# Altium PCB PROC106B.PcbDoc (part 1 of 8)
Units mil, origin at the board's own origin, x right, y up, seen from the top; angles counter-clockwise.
Board outline 4498.18 x 1060.53 mil, 8 copper layers (Top Layer, GND1, Sig1, PWR1, PWR2, Sig2, GND2, Bottom Layer), stack 69.602 mil thick; 439 components, 327 nets, 1548 pads, 843 vias.
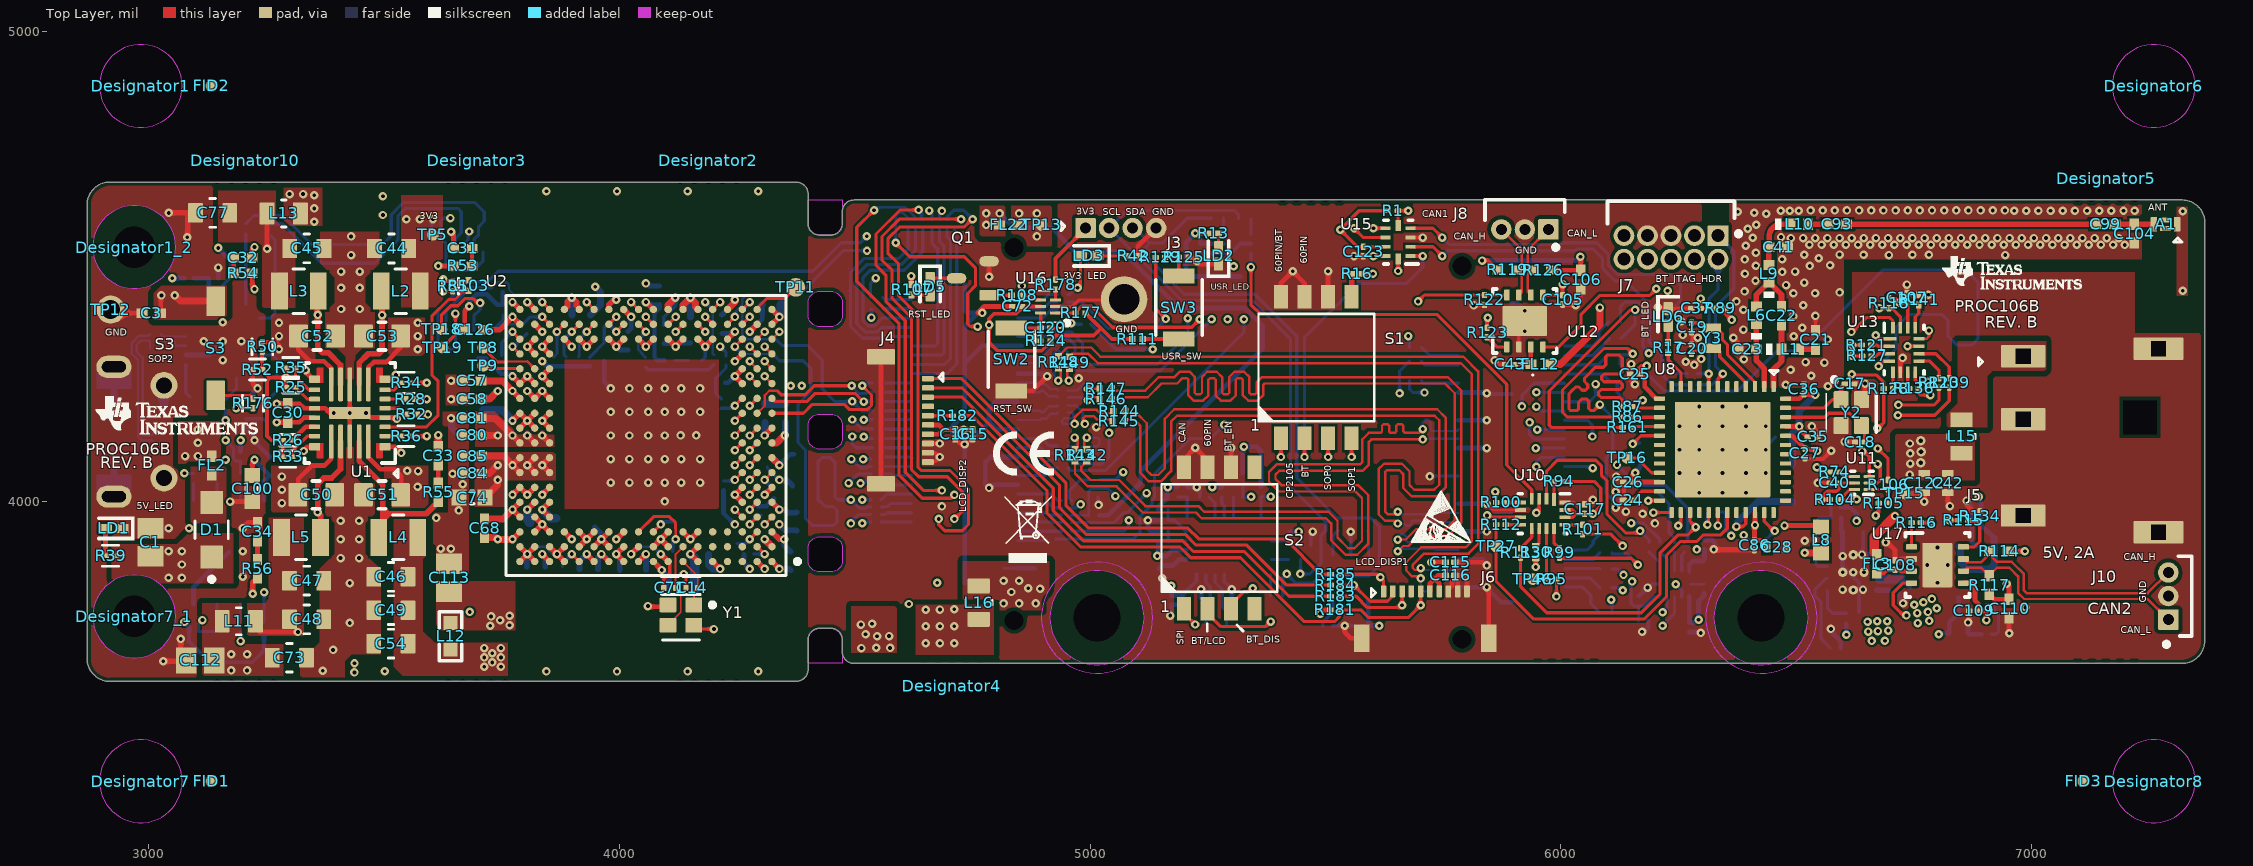
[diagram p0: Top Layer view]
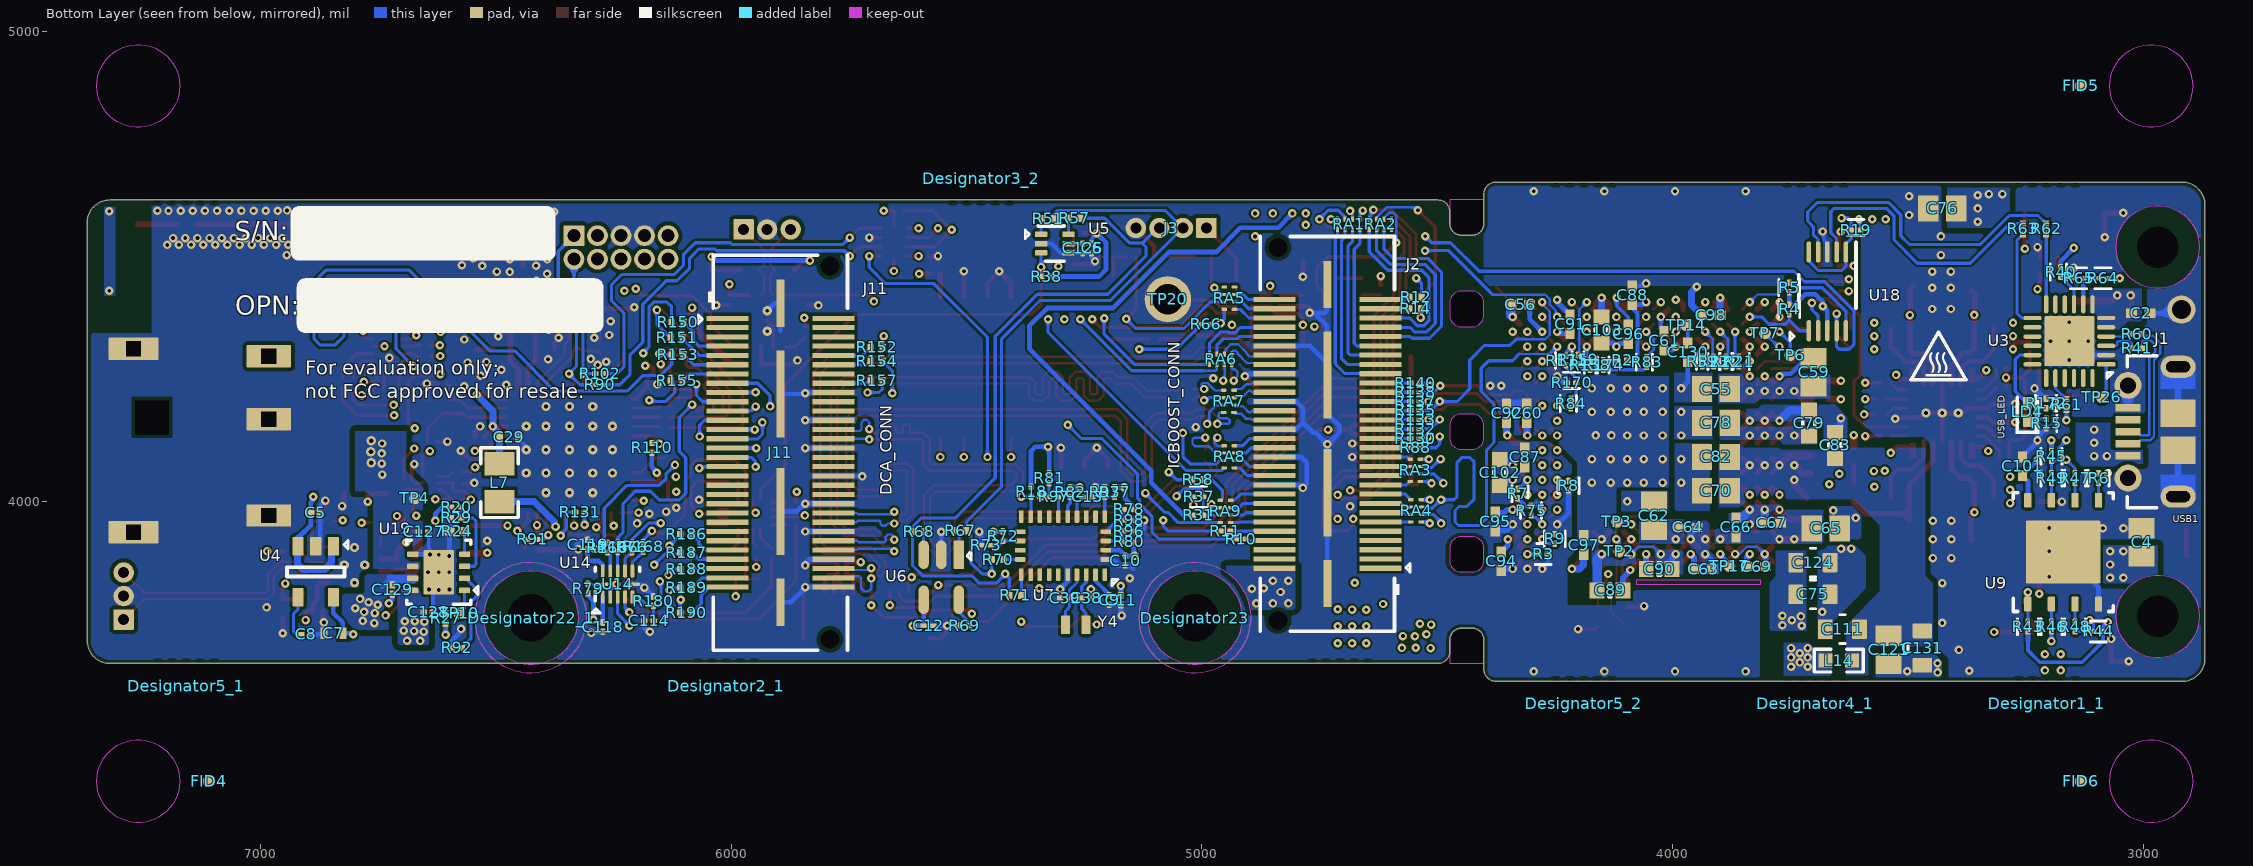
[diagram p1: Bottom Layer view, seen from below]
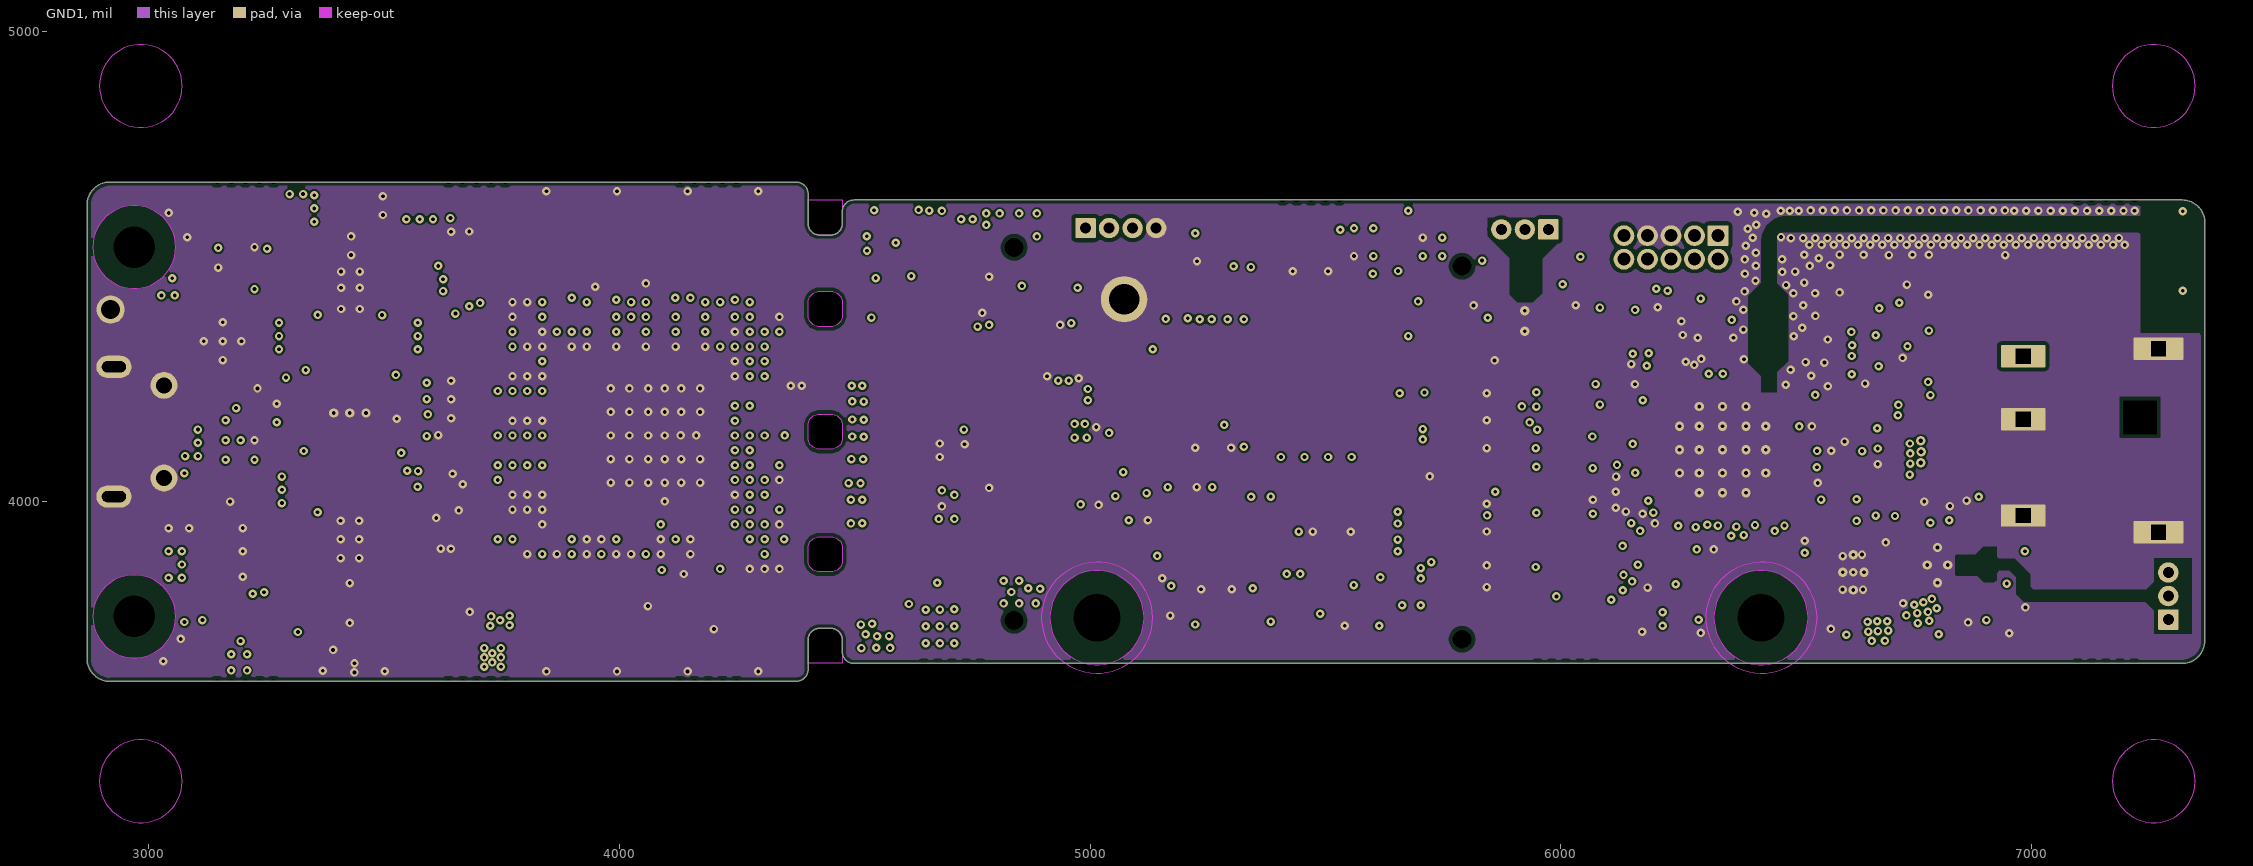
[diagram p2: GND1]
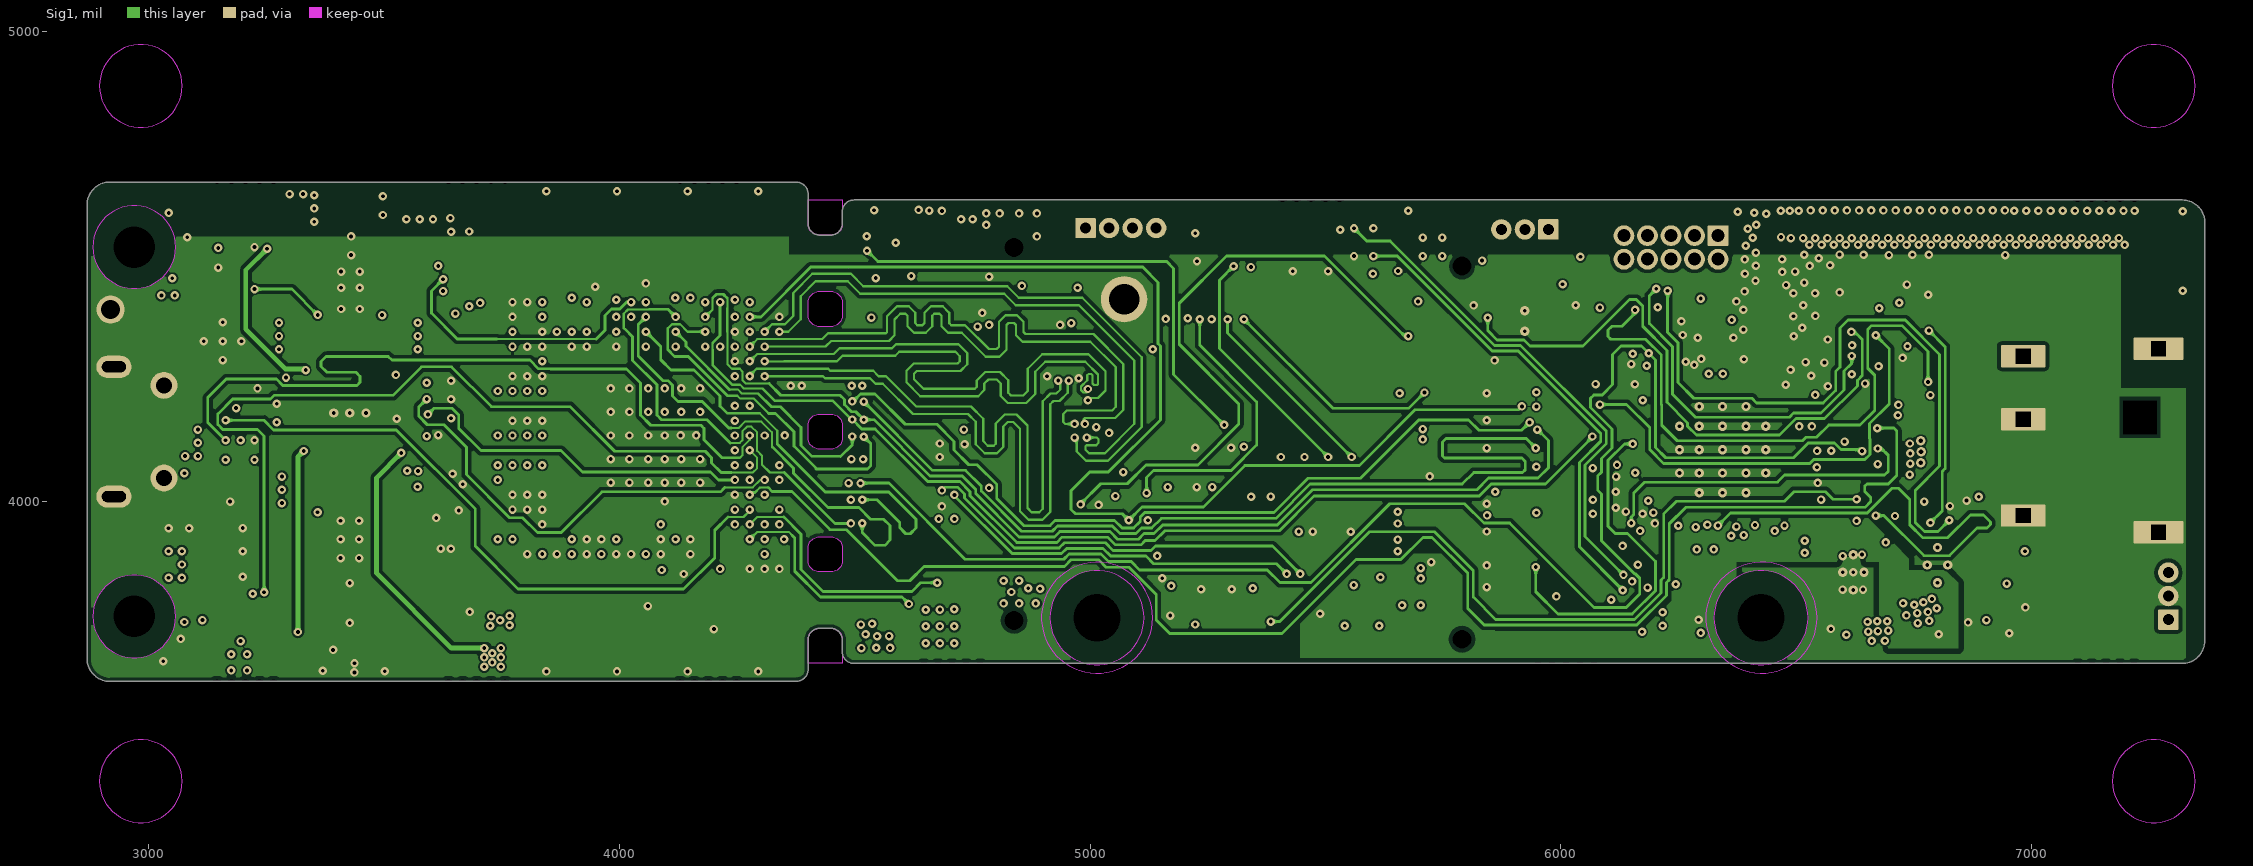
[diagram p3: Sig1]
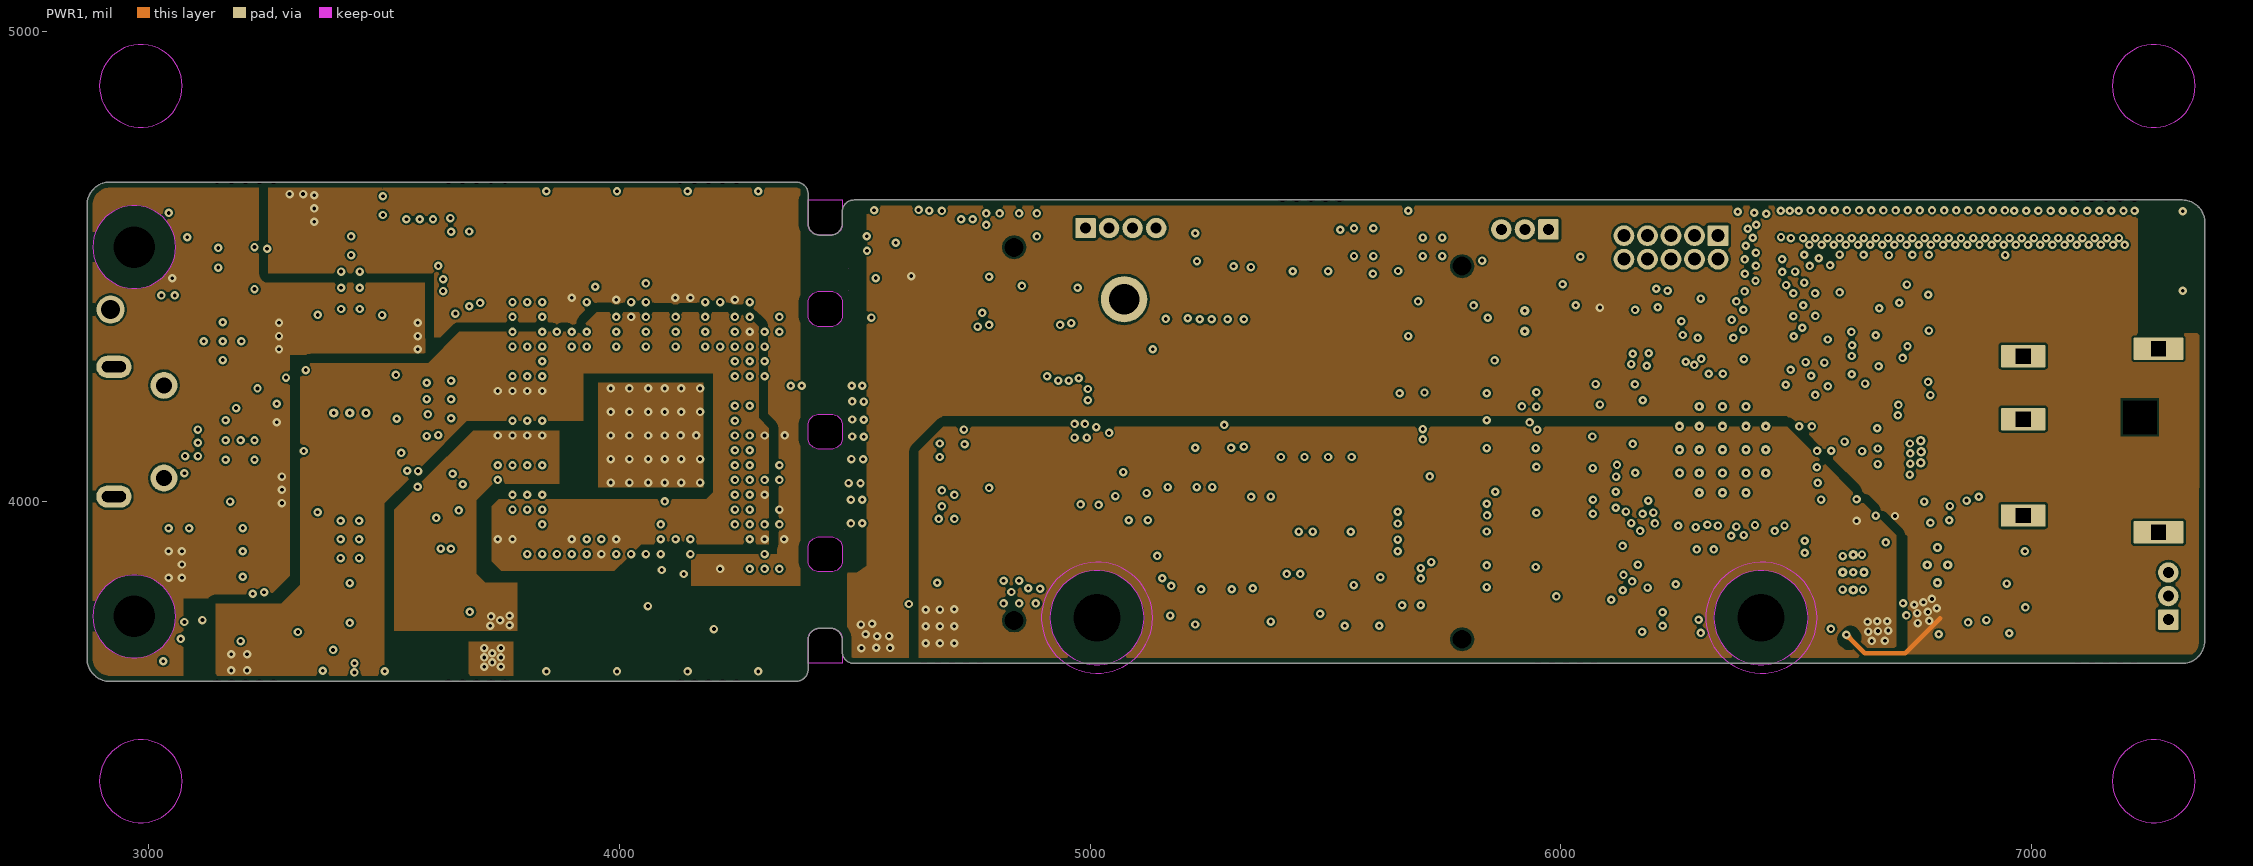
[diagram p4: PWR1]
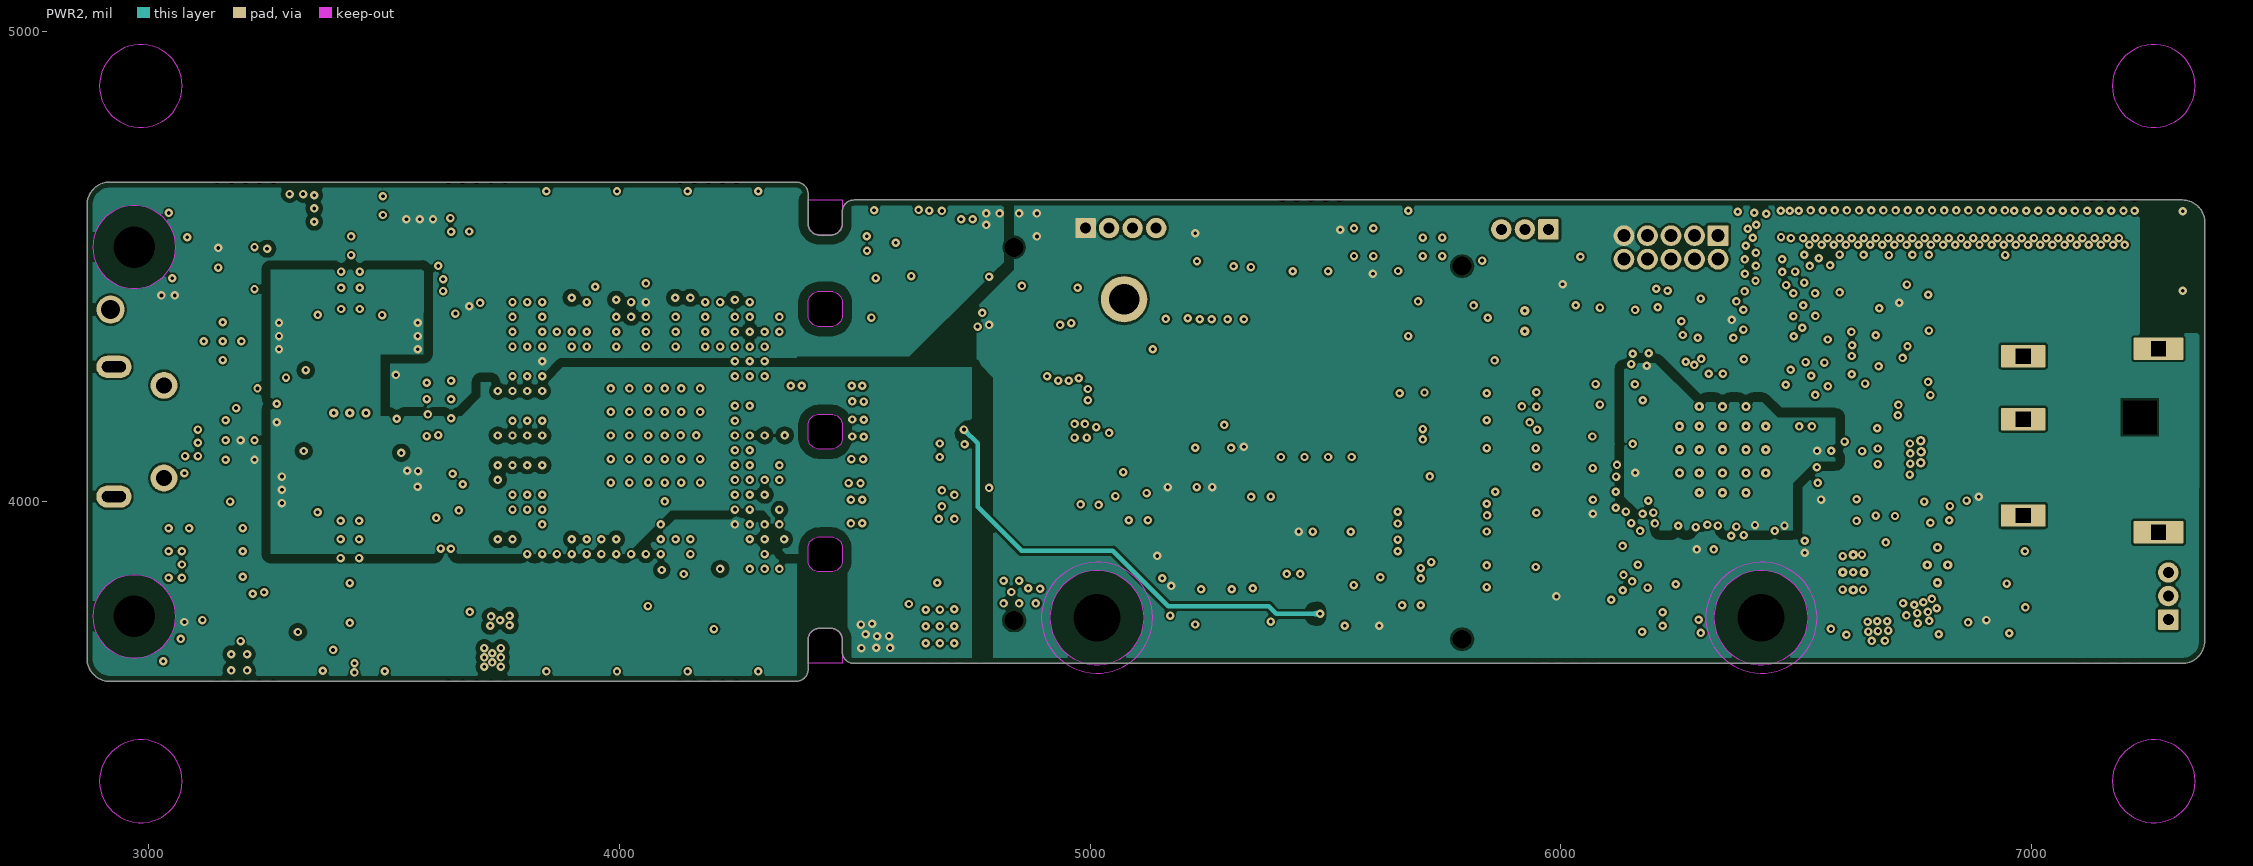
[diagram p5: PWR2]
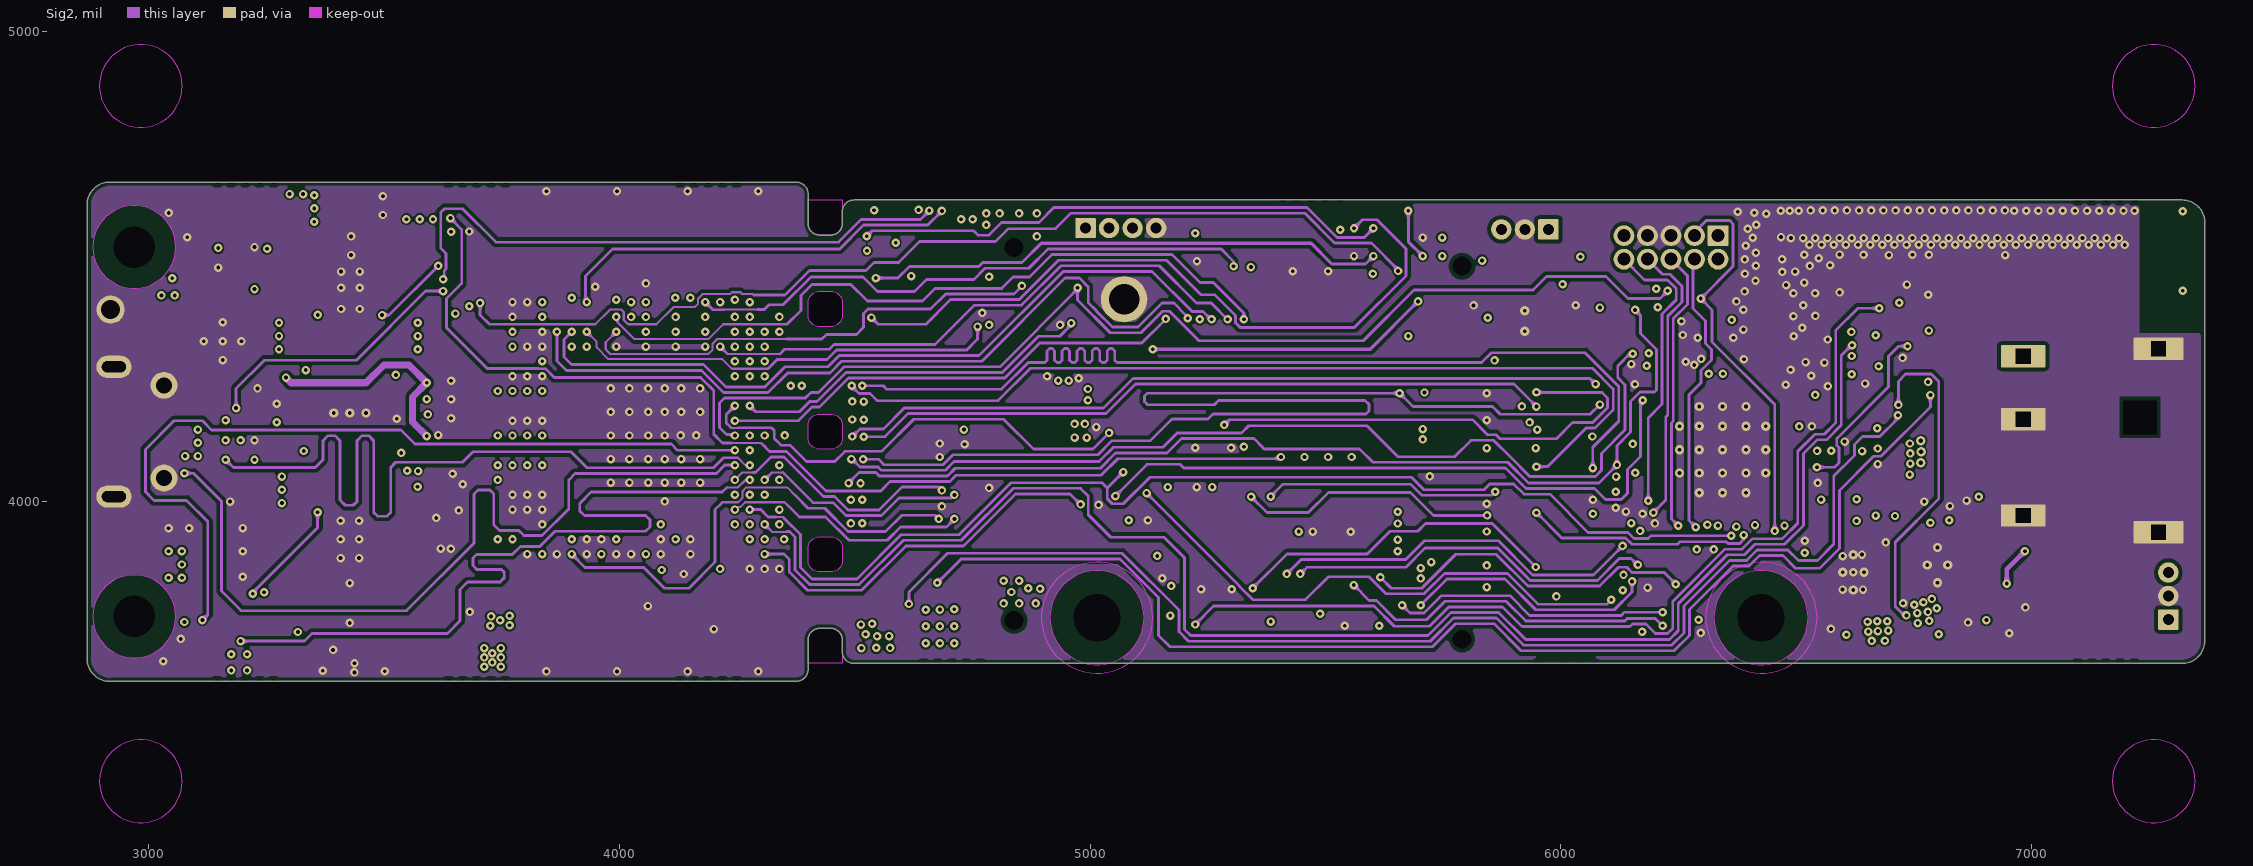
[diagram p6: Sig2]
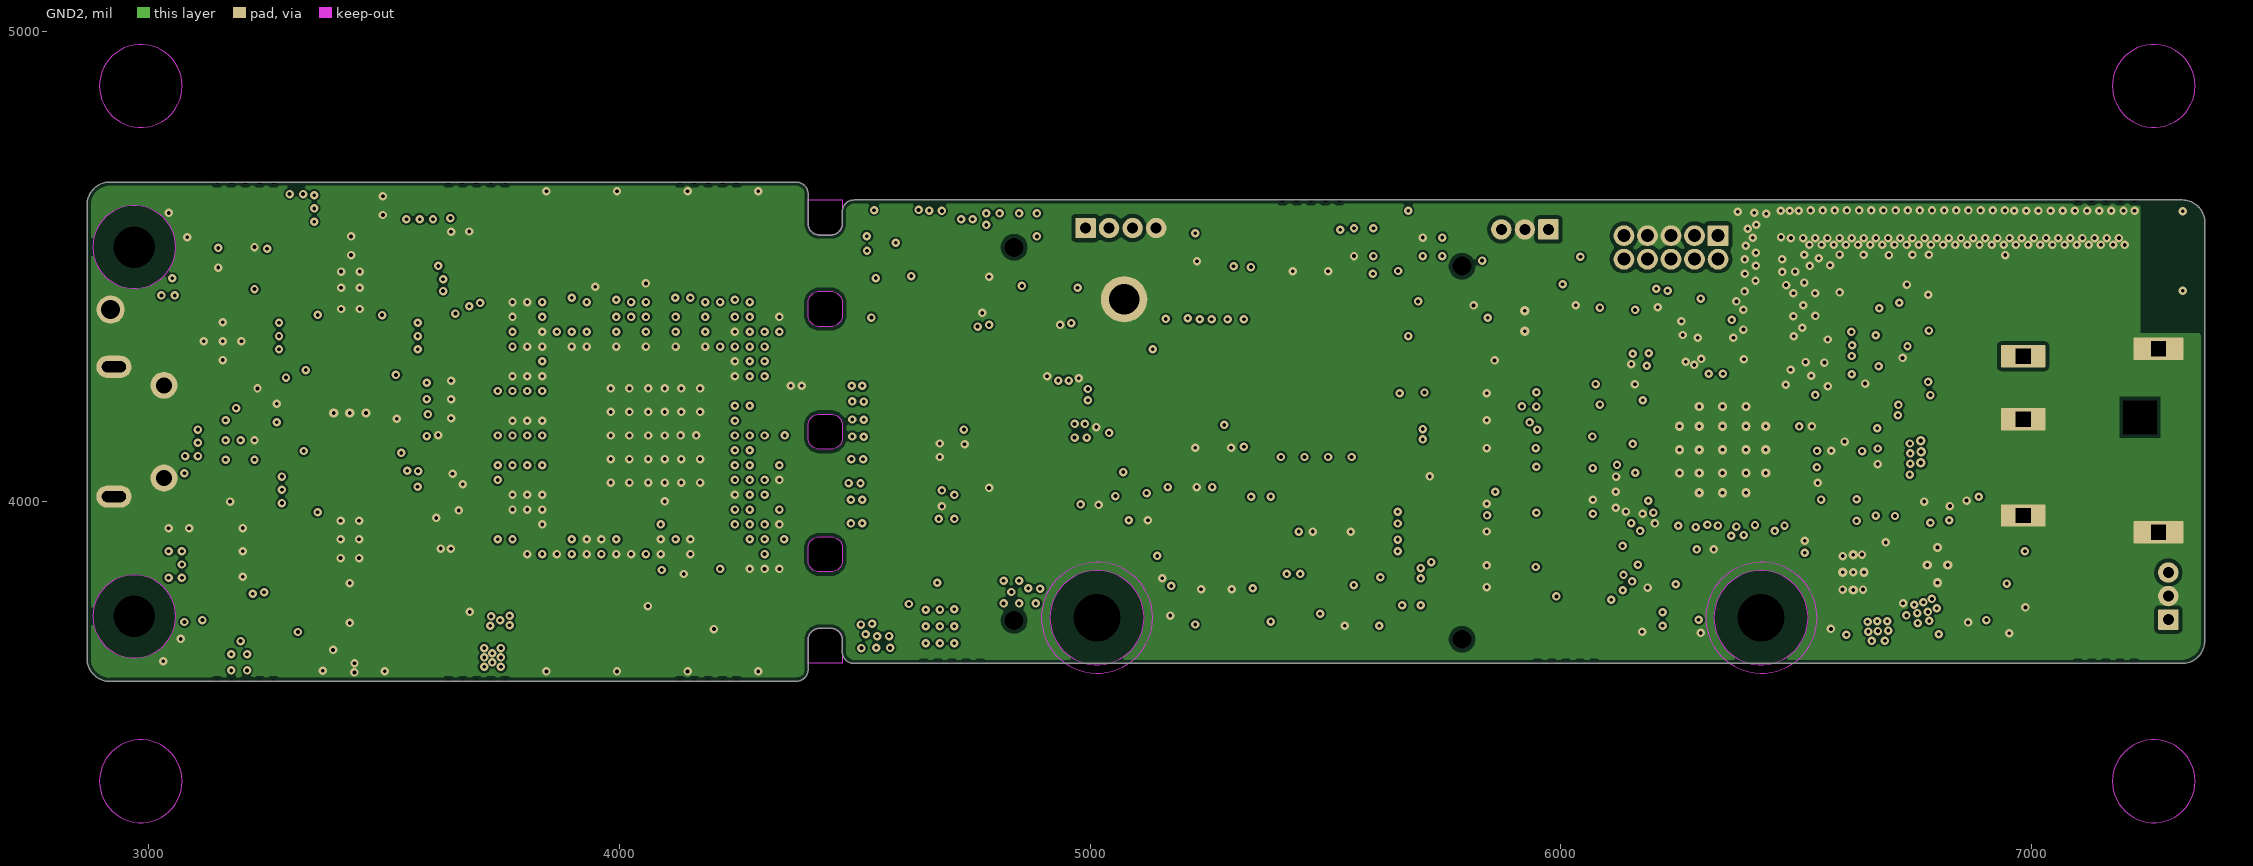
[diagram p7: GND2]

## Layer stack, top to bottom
Top Solder: solder mask 2, Solder Resist, Dk 3.9
Top Layer: signal copper 2.756
Dielectric1: prepreg 1.681, PP-006, Dk 3.79
Dielectric 1: prepreg 2.558, PP-006, Dk 3.86
GND1: signal copper 2.638
Dielectric3: core 12, Core-009, Dk 4.47
Sig1: signal copper 2.638
Dielectric2: prepreg 2.696, PP-006, Dk 4.13
Dielectric 3: prepreg 2.696, PP-006, Dk 4.13
PWR1: signal copper 2.638
Dielectric4: core 5, Core-009, Dk 4.21
PWR2: signal copper 2.638
Dielectric5: prepreg 2.696, PP-006, Dk 4.13
Dielectric 4: prepreg 2.696, PP-006, Dk 4.13
Sig2: signal copper 2.638
Dielectric8: core 12, Core-009, Dk 4.47
GND2: signal copper 2.638
Dielectric9: prepreg 2.558, PP-006, Dk 3.86
Dielectric 2: prepreg 1.681, PP-006, Dk 3.79
Bottom Layer: signal copper 2.756
Bottom Solder: solder mask 2, Solder Resist, Dk 3.9

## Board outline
2917.58,3618.9 4375.86,3618.9 4375.86,3619 ccw(c4375.86,3644) 4400.86,3644 4400.86,3706.52 cw(c4425.86,3706.52) 4425.86,3731.52 4448.63,3731.52 cw(c4448.63,3706.52) 4473.63,3706.52 4473.63,3681.91 4473.47,3681.91 ccw(c4498.47,3681.91) 4498.47,3656.91 4498.47,3656.87 7319.49,3656.87 ccw(c7319.49,3704.87) 7367.49,3704.87 7367.49,3704.83 7367.76,4593.42 7367.75,4593.44 ccw(c7319.76,4593.44) 7319.76,4641.43 4498.47,4641.43 4498.47,4641.39 ccw(c4498.47,4616.39) 4473.47,4616.39 4473.63,4591.77 cw(c4448.63,4591.77) 4448.63,4566.77 4425.86,4566.77 cw(c4425.86,4591.77) 4400.86,4591.77 4400.86,4654.3 ccw(c4375.86,4654.3) 4375.86,4679.3 4375.28,4679.43 2917.58,4679.43 ccw(c2917.58,4631.43) 2869.58,4631.43 2869.58,3666.9 ccw(c2917.58,3666.9)
cut-out: 4448.63,4111.81 4420.89,4111.81 4411.7,4115.62 4404.67,4122.65 4400.86,4131.84 4400.86,4136.81 4400.86,4161.47 4400.86,4166.44 4404.67,4175.63 4411.7,4182.66 4420.89,4186.47 4425.86,4186.47 4453.6,4186.47 4462.79,4182.66 4469.82,4175.63 4473.63,4166.44 4473.63,4161.47 4473.63,4136.81 4473.63,4131.84 4469.82,4122.65 4462.79,4115.62 4453.6,4111.81 4448.63,4111.81
cut-out: 4425.86,4447.12 4453.6,4447.12 4462.79,4443.32 4469.82,4436.28 4473.63,4427.1 4473.63,4422.12 4473.63,4397.47 4473.63,4392.5 4469.82,4383.31 4462.79,4376.28 4453.6,4372.47 4448.63,4372.47 4420.89,4372.47 4411.7,4376.28 4404.67,4383.31 4400.86,4392.5 4400.86,4397.47 4400.86,4422.12 4400.86,4427.1 4404.67,4436.28 4411.7,4443.32 4420.89,4447.12 4425.86,4447.12
cut-out: 4448.63,3851.17 4420.89,3851.17 4411.7,3854.98 4404.67,3862.01 4400.86,3871.2 4400.86,3876.17 4400.86,3900.82 4400.86,3905.8 4404.67,3914.98 4411.7,3922.02 4420.89,3925.82 4425.86,3925.82 4453.6,3925.82 4462.79,3922.02 4469.82,3914.98 4473.63,3905.8 4473.63,3900.82 4473.63,3876.17 4473.63,3871.2 4469.82,3862.01 4462.79,3854.98 4453.6,3851.17 4448.63,3851.17
cut-out: 4486.41,4450.17
cut-out: 4477.74,3942.38
cut-out: 4473.63,4641.43 4473.63,4604.1 4473.63,4591.77 4473.63,4586.8 4469.82,4577.61 4462.79,4570.58 4453.6,4566.77 4448.63,4566.77 4420.89,4566.77 4411.7,4570.58 4404.67,4577.61 4400.86,4586.8 4400.86,4591.77 4400.86,4604.1 4400.86,4641.43
cut-out: 4473.63,3656.87 4453.6,3656.87 4400.86,3656.87 4400.86,3711.49 4404.67,3720.68 4411.7,3727.71 4420.89,3731.52 4425.86,3731.52 4453.6,3731.52 4462.79,3727.71 4469.82,3720.68 4473.63,3711.49 4473.63,3706.52 4473.63,3691.71
cut-out: 4486.41,4495.33

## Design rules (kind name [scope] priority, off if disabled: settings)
AcuteAngle [All] p1: minimum=4.50000000000000E+0001 checktracksonly=TRUE
AssemblyTestPointUsage [All] p1: valid=2
BoardOutlineClearance BoardOutlineClearance_1 [InNet('GND')] p1: gap=8 ignorepadtopadclearanceinfootprint=FALSE
BoardOutlineClearance [NOT((OnTopSilkscreen OR OnBottomSilkscreen)OR InComponentClass('FiducialMark') or InPadClass('Non Plated'))] p2: gap=12 ignorepadtopadclearanceinfootprint=FALSE except(0: Text-OutlineEdge)
Clearance Keepout [(OnLayer('Keep-Out Layer'))] p1: gap=0.01 ignorepadtopadclearanceinfootprint=FALSE except(5.9: THPad-THPad; 7: Arc-THPad Track-THPad THPad-Via; 8: THPad-Fill THPad-Poly THPad-Region)
Clearance RF_TRACE [InNetClass('RF')] p2: gap=4 ignorepadtopadclearanceinfootprint=FALSE except(0: Arc-Hole Track-Hole SMDPad-Hole THPad-Hole Via-Hole Fill-Hole Poly-Hole Region-Hole Text-Hole; 2: Arc-Text Track-Text SMDPad-Text THPad-Text Via-Text Fill-Text Poly-Text Region-Text Text-Text; 4.8: Track-Poly; 5: Arc-Fill Arc-Poly Arc-Region Track-Fill Track-Region; 5.9: THPad-THPad; 6: SMDPad-Fill SMDPad-Poly SMDPad-Region Via-Fill Via-Poly Via-Region; 7: Arc-THPad Track-THPad THPad-Via; 8: THPad-Fill THPad-Poly THPad-Region; 15: Fill-Fill Fill-Poly Fill-Region Poly-Poly Poly-Region Region-Region)
Clearance AOP_T-B [WithinRoom('BGA') vs (OnLayer('Bottom Layer') or OnLayer('Top Layer'))] p3: gap=4 ignorepadtopadclearanceinfootprint=TRUE except(0: Arc-Hole Track-Hole SMDPad-Hole THPad-Hole Via-Hole Fill-Hole Poly-Hole Region-Hole Text-Hole; 5.9: THPad-THPad; 7: Arc-THPad Track-THPad THPad-Via; 8: THPad-Fill THPad-Poly THPad-Region Fill-Fill Fill-Poly Fill-Region Poly-Poly Region-Region)
Clearance AOP_Sig [WithinRoom('BGA') vs (OnLayer('sig1') or OnLayer('sig2'))] p4: gap=4 ignorepadtopadclearanceinfootprint=FALSE except(0: Arc-Hole Track-Hole SMDPad-Hole THPad-Hole Via-Hole Fill-Hole Poly-Hole Region-Hole Text-Hole; 3.5: Arc-Text Track-Text SMDPad-Text THPad-Text Via-Via Via-Text Fill-Text Poly-Text Region-Text Text-Text; 3.8: SMDPad-Via; 4.5: Arc-Via Track-Via; 5.9: THPad-THPad; 7: Arc-THPad Track-THPad THPad-Via; 8: Arc-Fill Arc-Poly Arc-Region Track-Fill Track-Poly Track-Region SMDPad-THPad THPad-Fill THPad-Poly THPad-Region; 15: Fill-Fill Fill-Poly Fill-Region Poly-Poly Region-Region)
Clearance 100E [InDifferentialPairClass('100E') vs (OnLayer('Sig1') or OnLayer('Sig2'))] p5: gap=8 ignorepadtopadclearanceinfootprint=TRUE except(0: Arc-Hole Track-Hole SMDPad-Hole THPad-Hole Via-Hole Fill-Hole Poly-Hole Region-Hole Text-Hole; 2: Arc-Text Track-Text THPad-Text Via-Text Fill-Text Poly-Text Region-Text Text-Text; 4: Arc-SMDPad Track-SMDPad SMDPad-SMDPad SMDPad-THPad SMDPad-Via SMDPad-Text Via-Fill Via-Poly Via-Region; 4.5: Arc-Via Track-Via; 5.9: THPad-THPad; 6: SMDPad-Fill SMDPad-Poly SMDPad-Region Fill-Fill Fill-Poly Fill-Region Poly-Poly Poly-Region Region-Region; 7: Arc-THPad Track-THPad THPad-Via; 11: Arc-Arc Arc-Track Track-Track)
Clearance 100E_1 [InDifferentialPairClass('100E') vs (OnLayer('Bottom Layer') or OnLayer('Top Layer'))] p6: gap=8 ignorepadtopadclearanceinfootprint=FALSE except(0: Arc-Hole Track-Hole SMDPad-Hole THPad-Hole Via-Hole Fill-Hole Poly-Hole Region-Hole Text-Hole; 2: Arc-Text Track-Text THPad-Text Via-Text Fill-Text Poly-Text Region-Text Text-Text; 4: Arc-SMDPad Track-SMDPad SMDPad-SMDPad SMDPad-THPad SMDPad-Via SMDPad-Text Via-Fill Via-Poly Via-Region; 5: Arc-Via Track-Via; 5.9: THPad-THPad; 6: SMDPad-Fill SMDPad-Poly SMDPad-Region Fill-Fill Fill-Poly Fill-Region Poly-Poly Poly-Region Region-Region; 7: Arc-THPad Track-THPad THPad-Via; 10.65: Arc-Arc Arc-Track Track-Track)
Clearance 50E_INNERlayer [(OnLayer('sig1') or OnLayer('Sig2'))] p7: gap=4.2 ignorepadtopadclearanceinfootprint=TRUE except(0: Arc-Hole Track-Hole SMDPad-Hole THPad-Hole Via-Hole Fill-Hole Poly-Hole Region-Hole Text-Hole; 2: SMDPad-Text Fill-Text Poly-Text Region-Text Text-Text; 4: Via-Fill Via-Poly Via-Region Poly-Region; 4.35: Arc-Via Track-Via; 5.9: THPad-THPad; 5.95: Arc-Arc Arc-Track Track-Track; 6: SMDPad-Fill SMDPad-Poly SMDPad-Region; 7: Arc-THPad Track-THPad THPad-Via; 8: Arc-Fill Arc-Poly Arc-Region Track-Fill Track-Poly Track-Region THPad-Fill THPad-Poly THPad-Region; 12: Fill-Fill Fill-Poly Fill-Region Poly-Poly Region-Region)
Clearance PWR_20 [(OnLayer('pwr2')) vs InNetClass('PWR')] p8: gap=8 ignorepadtopadclearanceinfootprint=TRUE except(0: Arc-Hole Track-Hole SMDPad-Hole THPad-Hole Via-Hole Fill-Hole Poly-Hole Region-Hole Text-Hole; 2: SMDPad-Text Fill-Text Poly-Text Region-Text Text-Text; 4.2: Arc-Text Track-Text THPad-Text Via-Via Via-Text; 5: THPad-Fill THPad-Poly THPad-Region; 5.9: THPad-THPad; 6: Arc-Via Arc-Fill Arc-Poly Arc-Region Track-Via Track-Fill Track-Poly Track-Region; 7: THPad-Via; 10: Via-Fill Via-Poly Via-Region; 20: Fill-Fill Fill-Poly Fill-Region Poly-Poly Poly-Region Region-Region)
Clearance INNERlayer [(OnLayer('pwr1') or OnLayer('pwr2'))] p9: gap=8 ignorepadtopadclearanceinfootprint=TRUE except(0: Arc-Hole Track-Hole SMDPad-Hole THPad-Hole Via-Hole Fill-Hole Poly-Hole Region-Hole Text-Hole; 2: SMDPad-Text Fill-Text Poly-Text Region-Text Text-Text; 4: Via-Fill Via-Poly Via-Region; 4.2: Arc-Text Track-Text THPad-Text Via-Via Via-Text; 5: THPad-Fill THPad-Poly THPad-Region; 5.9: THPad-THPad; 6: Arc-Via Arc-Fill Arc-Poly Arc-Region Track-Via Track-Fill Track-Poly Track-Region; 7: THPad-Via; 20: Fill-Fill Fill-Poly Fill-Region Poly-Poly Poly-Region Region-Region)
Clearance 90E_OUTSIDE [InDifferentialPairClass('90E') vs OnOutside] p10: gap=6 ignorepadtopadclearanceinfootprint=TRUE except(0: Arc-Hole Track-Hole SMDPad-Hole THPad-Hole Via-Hole Fill-Fill Fill-Poly Fill-Region Fill-Hole Poly-Poly Poly-Region Poly-Hole Region-Region Region-Hole Text-Hole; 2: Arc-Text Track-Text SMDPad-Text THPad-Text Via-Text Fill-Text Poly-Text Region-Text Text-Text; 4: Arc-SMDPad Track-SMDPad SMDPad-SMDPad Via-Via Via-Fill Via-Poly Via-Region; 4.5: Arc-Arc Arc-Track Arc-Via Track-Track Track-Via; 5.9: THPad-THPad; 7: Arc-THPad Track-THPad SMDPad-THPad THPad-Via; 8: SMDPad-Via THPad-Fill THPad-Poly THPad-Region)
Clearance [All] p11: gap=1 ignorepadtopadclearanceinfootprint=TRUE except(0: Arc-Hole Track-Hole SMDPad-Hole THPad-Hole Via-Hole Fill-Hole Poly-Hole Region-Hole Text-Hole; 4: Arc-SMDPad Track-SMDPad SMDPad-SMDPad SMDPad-Via Via-Via Via-Fill Via-Poly Via-Region Poly-Region; 4.2: Arc-Via Track-Via; 5: Arc-Fill Arc-Poly Arc-Region Track-Fill Track-Poly Track-Region; 5.85: Arc-Arc Arc-Track Track-Track; 5.9: THPad-THPad; 6: SMDPad-Fill SMDPad-Poly SMDPad-Region; 7: Arc-THPad Track-THPad SMDPad-THPad THPad-Via; 8: THPad-Fill THPad-Poly THPad-Region; 12: Fill-Fill Fill-Poly Fill-Region Poly-Poly Region-Region)
Clearance "SAME NET" [All] p12: gap=0 ignorepadtopadclearanceinfootprint=FALSE except(0.5: SMDPad-Text; 5.9: THPad-THPad)
ComponentClearance ComponentClearance_R199_187 [InComponent('J11') or InComponent('TP20')] p1: gap=-1 collisioncheckmode=3 verticalgap=10 showdistances=FALSE
ComponentClearance ComponentClearance_R188_204 [InComponent('R188') vs InComponent('R204')] p2: gap=-1 collisioncheckmode=3 verticalgap=10 showdistances=FALSE
ComponentClearance [All] p3: gap=1 collisioncheckmode=3 verticalgap=10 showdistances=FALSE
ComponentClearance ComponentClearance_MountingHoles_FiducialMarks [InComponentClass('Mounting Holes') vs InComponentClass('FiducialMark')] p4: gap=50 collisioncheckmode=3 verticalgap=10 showdistances=FALSE
ComponentClearance ComponentClearance_Shunt [InComponentClass('Header') vs InComponentClass('Shunt')] p5: gap=1 collisioncheckmode=3 verticalgap=0 showdistances=FALSE
ComponentClearance ComponentClearance_Logo [InComponentClass('Logo')] p6: gap=50 collisioncheckmode=3 verticalgap=10 showdistances=FALSE
ComponentClearance ComponentClearance_ScrewToNut [(HasFootprint('NY PMS 440 0025 PH')) vs (HasFootprint('Keystone_1902C'))] p7: gap=5 collisioncheckmode=3 verticalgap=10 showdistances=FALSE
ComponentClearance ComponentClearance_MountingHoles [InComponentClass('Mounting Holes')] p8: gap=20 collisioncheckmode=3 verticalgap=100000 showdistances=FALSE
ComponentClearance ComponentClearance_SmallPassives [HasFootprint('0201*') or HasFootprint('0402*') or HasFootprint('0508') or HasFootprint('0603*') or HasFootprint('0612') or HasFootprint('0805*') or HasFootprint('0815*') or HasFootprint('0830*') or HasFootprint('1206*') or HasFootprint('1210*') or HasFootprint('1808*') or HasFootprint('1812*') or HasFootprint('1825*') or HasFootprint('2010*') or HasFootprint('2220*') or HasFootprint('2225*') or HasFootprint('2512*') or HasFootprint('2728*') or HasFootprint('3518*') vs HasFootprint('0201*') or HasFootprint('0402*') or HasFootprint('0508') or HasFootprint('0603*') or HasFootprint('0612') or HasFootprint('0805*') or HasFootprint('0815*') or HasFootprint('0830*') or HasFootprint('1206*') or HasFootprint('1210*') or HasFootprint('1808*') or HasFootprint('1812*') or HasFootprint('1825*') or HasFootprint('2010*') or HasFootprint('2220*') or HasFootprint('2225*') or HasFootprint('2512*') or HasFootprint('2728*') or HasFootprint('3518*')] p9: gap=10 collisioncheckmode=3 verticalgap=10 showdistances=FALSE
ComponentClearance ComponentClearance_THtoSMT [IsThruComponent vs IsSMTComponent] p10: gap=5 collisioncheckmode=3 verticalgap=20 showdistances=FALSE
ComponentClearance ComponentClearance_THtoTH [IsThruComponent vs IsThruComponent] p11: gap=20 collisioncheckmode=3 verticalgap=30 showdistances=FALSE
DiffPairsRouting Diff_100E [InDifferentialPairClass('100E')] p1: maxlimit=11.2 minlimit=8.6 mostfreqgap=10 toplayer_maxgap=8.6 toplayer_prefgap=8.6 toplayer_minwidth=5.1 toplayer_maxwidth=5.1 toplayer_prefwidth=5.1 midlayer1_mingap=10 midlayer1_maxgap=10 midlayer1_minwidth=15 midlayer1_maxwidth=15 midlayer1_prefwidth=15 midlayer2_mingap=11.2 midlayer2_prefgap=11.2 midlayer2_minwidth=4.5 midlayer2_maxwidth=4.8 midlayer2_prefwidth=4.8 midlayer3_mingap=10 midlayer3_maxgap=10 midlayer3_minwidth=15 midlayer3_maxwidth=15 midlayer3_prefwidth=15 midlayer6_mingap=10 midlayer6_maxgap=10 midlayer6_minwidth=15 midlayer6_maxwidth=15 midlayer6_prefwidth=15 midlayer7_mingap=11.2 midlayer7_prefgap=11.2 midlayer7_minwidth=4.5 midlayer7_maxwidth=4.8 midlayer7_prefwidth=4.8 midlayer8_mingap=10 midlayer8_maxgap=10 midlayer8_minwidth=15 midlayer8_maxwidth=15 midlayer8_prefwidth=15 bottomlayer_maxgap=8.6 bottomlayer_prefgap=8.6 bottomlayer_minwidth=5.1 bottomlayer_maxwidth=5.1 bottomlayer_prefwidth=5.1 maxuncoupledlength=500
DiffPairsRouting Diff_90E [InDifferentialPairClass('90E')] p2: maxlimit=100 minlimit=5 mostfreqgap=10 toplayer_maxgap=5 toplayer_prefgap=5 toplayer_minwidth=5 toplayer_maxwidth=5 toplayer_prefwidth=5 midlayer1_mingap=10 midlayer1_minwidth=15 midlayer1_maxwidth=15 midlayer1_prefwidth=15 midlayer2_mingap=7.4 midlayer2_maxgap=7.4 midlayer2_prefgap=7.4 midlayer2_minwidth=5 midlayer2_maxwidth=5 midlayer2_prefwidth=5 midlayer3_mingap=10 midlayer3_minwidth=15 midlayer3_maxwidth=15 midlayer3_prefwidth=15 midlayer6_mingap=10 midlayer6_minwidth=15 midlayer6_maxwidth=15 midlayer6_prefwidth=15 midlayer7_mingap=7.4 midlayer7_maxgap=7.4 midlayer7_prefgap=7.4 midlayer7_minwidth=5 midlayer7_maxwidth=5 midlayer7_prefwidth=5 midlayer8_mingap=10 midlayer8_minwidth=15 midlayer8_maxwidth=15 midlayer8_prefwidth=15 bottomlayer_maxgap=5 bottomlayer_prefgap=5 bottomlayer_minwidth=5 bottomlayer_maxwidth=5 bottomlayer_prefwidth=5 maxuncoupledlength=1000
DiffPairsRouting Diff_120E [InDifferentialPairClass('120E')] p3: maxlimit=10 minlimit=6.1 mostfreqgap=10 toplayer_mingap=7.15 toplayer_maxgap=7.15 toplayer_prefgap=7.15 toplayer_minwidth=5.2 toplayer_maxwidth=5.2 toplayer_prefwidth=5.2 midlayer1_mingap=10 midlayer1_minwidth=15 midlayer1_maxwidth=15 midlayer1_prefwidth=15 midlayer2_mingap=10 midlayer2_minwidth=15 midlayer2_maxwidth=15 midlayer2_prefwidth=15 midlayer3_mingap=10 midlayer3_minwidth=15 midlayer3_maxwidth=15 midlayer3_prefwidth=15 midlayer6_mingap=10 midlayer6_minwidth=15 midlayer6_maxwidth=15 midlayer6_prefwidth=15 midlayer7_mingap=10 midlayer7_minwidth=15 midlayer7_maxwidth=15 midlayer7_prefwidth=15 midlayer8_mingap=10 midlayer8_minwidth=15 midlayer8_maxwidth=15 midlayer8_prefwidth=15 bottomlayer_maxgap=6.1 bottomlayer_prefgap=6.1 bottomlayer_minwidth=4 bottomlayer_maxwidth=4 bottomlayer_prefwidth=4 maxuncoupledlength=500
FabricationTestPointUsage TestPointUsage [All] p1: valid=2 allowmultiple=FALSE
FabricationTestpoint Testpoint [All] p1: side=3 testpointundercomponent=TRUE minsize=40 maxsize=100 preferedsize=60 minholesize=0 maxholesize=40 preferedholesize=32 testpointgrid=1 allowsidetop=TRUE allowsidebottom=TRUE usegrid=TRUE gridtolerance=0.01
FanoutControl Fanout_LCC [IsLCC] p1: bgadir=Out bgaviamode=Centered fanoutstyle=Auto fanoutdirection=Alternating viagrid=1 // Fanout_LCC (Default Rule)
FanoutControl Fanout_BGA [IsBGA] p2: bgadir=Out bgaviamode=Centered fanoutstyle=Auto fanoutdirection=Alternating viagrid=1 // Fanout_BGA (Default Rule)
FanoutControl Fanout_Default [All] p4: bgadir=Out bgaviamode=Centered fanoutstyle=Auto fanoutdirection=Alternating viagrid=1 // Fanout_Default (Default Rule)
FanoutControl Fanout_Small [(CompPinCount < 5)] p5: bgadir=Out bgaviamode=Centered fanoutstyle=Auto fanoutdirection=OutThenIn viagrid=1 // Fanout_Small (Default Rule)
HoleSize [All] p1: absolutevalues=TRUE maxlimit=251 minlimit=5.9 maxpercent=80.000 minpercent=20.000
HoleToHoleClearance [All and  (not InPadClass('Non Plated'))] p1: gap=10 allowstackedmicrovias=TRUE
MatchedLengths U13-J11 [InxSignalClass('U13-J11')] p1: tolerance=400 checknetsindiffpair=FALSE checkdiffpairvsdiffpair=TRUE checkxsignals=TRUE checkothers=TRUE
MatchedLengths U13-J2 [InxSignalClass('U13-J2')] p2: tolerance=400 checknetsindiffpair=FALSE checkdiffpairvsdiffpair=TRUE checkxsignals=TRUE checkothers=TRUE
MatchedLengths U13-U8 [InxSignalClass('U13-U8')] p3: tolerance=400 checknetsindiffpair=FALSE checkdiffpairvsdiffpair=TRUE checkxsignals=TRUE checkothers=TRUE
MatchedLengths [InNetClass('LVDS_IC')] p4: tolerance=20 checknetsindiffpair=FALSE checkdiffpairvsdiffpair=TRUE checkxsignals=TRUE checkothers=TRUE
MatchedLengths USB [InxSignalClass('USB')] p5: tolerance=5 checknetsindiffpair=TRUE checkdiffpairvsdiffpair=FALSE checkxsignals=FALSE checkothers=FALSE
MatchedLengths QSPI [InxSignalClass('QSPI')] p6: tolerance=100 checknetsindiffpair=FALSE checkdiffpairvsdiffpair=TRUE checkxsignals=TRUE checkothers=TRUE
MatchedLengths SPI [InxSignalClass('SPI & HOSTINT')] p7: tolerance=200 checknetsindiffpair=FALSE checkdiffpairvsdiffpair=TRUE checkxsignals=TRUE checkothers=TRUE
MatchedLengths JTAG [InxSignalClass('JTAG')] p8: tolerance=100 checknetsindiffpair=FALSE checkdiffpairvsdiffpair=TRUE checkxsignals=TRUE checkothers=TRUE
MinimumAnnularRing MinimumAnnularRing_ThermalPadVias [IsVia and InAnyComponent] p1: minimumring=3
MinimumAnnularRing [All] p2: minimumring=3
MinimumSolderMaskSliver [All] p1: minsoldermaskwidth=2.9
PlaneConnect [All] p1: planeconnectstyle=Direct reliefexpansion=10 reliefentries=4 reliefconductorwidth=10 reliefairgap=10
PolygonConnect [All] p1: connectstyle=Direct reliefconductorwidth=10 reliefentries=4 polygonreliefangle="90 Angle" airgapwidth=10
RoomDefinition PROC106B_Hardware [InComponentClass('PROC106B_Hardware')] p1 off: confinementstyle=ConfineIn formatcopy=TRUE lockcomponents=FALSE outline 3741.3,4404.25 4366.16,4404.25 4366.16,3790.65 3740.45,3790.65
RoutingVias [All] p1: holewidth=8 width=18 viastyle="Through Hole" minholewidth=7.87 minwidth=17 maxholewidth=40 maxwidth=30
RoutingVias ThermalPadVias [IsVia and InAnyComponent] p2: holewidth=7.87 width=19.68 viastyle="Through Hole" minholewidth=7.87 minwidth=19.68 maxholewidth=12.99 maxwidth=23.62
SilkToBoardRegionClearance [Not ((IsComment or IsDesignator) And (Hide <> 'False')) and not InRegion(1000,500,4000,800)] p1:
SilkToSilkClearance [All] p1: silktosilkclearance=3
SilkToSolderMaskClearance SilkToComponentPadClearance [(IsPad or IsFill or IsRegion) and InAnycomponent] p1: minsilkscreentomaskgap=2 clearancetoexposedcopper=TRUE
SilkToSolderMaskClearance "Silk to Solder Mask Opening" [All] p2: minsilkscreentomaskgap=2 clearancetoexposedcopper=FALSE
SolderMaskExpansion [All] p1: expansion=1.97
Width RF [InNetClass('RF')] p1: maxlimit=100 minlimit=5.5 preferedwidth=10 toplayer_prefwidth=12 midlayer1_minwidth=10 midlayer1_maxwidth=10 midlayer2_minwidth=10 midlayer2_maxwidth=10 midlayer3_minwidth=10 midlayer3_maxwidth=10 midlayer6_minwidth=10 midlayer6_maxwidth=10 midlayer7_minwidth=10 midlayer7_maxwidth=10 midlayer8_minwidth=10 midlayer8_maxwidth=10 bottomlayer_minwidth=10 bottomlayer_maxwidth=10 minimp=50.000000 maximp=50.000000 favimp=50.000000
Width [All] p2: maxlimit=100 minlimit=4 preferedwidth=6 toplayer_maxwidth=40 toplayer_prefwidth=6.7 midlayer1_minwidth=4.2 midlayer1_maxwidth=20 midlayer1_prefwidth=4.2 midlayer2_minwidth=4.5 midlayer2_maxwidth=15 midlayer2_prefwidth=5.95 midlayer7_minwidth=4.5 midlayer7_maxwidth=15 midlayer7_prefwidth=5.95 midlayer8_minwidth=6 midlayer8_prefwidth=10 bottomlayer_maxwidth=40 bottomlayer_prefwidth=6.7 minimp=50.000000 maximp=50.000000 favimp=50.000000
14 further rules are at their usual default settings.

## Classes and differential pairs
pad class "Non Plated": Designator1_2- Designator7_1- Designator22_1- Designator23- FL2-1 FL2-2 FL3-1 FL3-2 FL12-1 FL12-2 FL22-1 FL22-2 Free-
net class PWR: AR_1P0_RF1 AR_1P0_RF2 AR_1P2 AR_1V4_APLL AR_1V4_SYNTH AR_1V8 PMIC_1V0 PMIC_1V2 PMIC_1V8
net class 100E: AR_LVDS_0_N AR_LVDS_0_P AR_LVDS_1_N AR_LVDS_1_P AR_LVDS_CLK_N AR_LVDS_CLK_P AR_LVDS_FRCLK_N AR_LVDS_FRCLK_P
net class RF: NetA1_4 NetC22_1 NetC41_1 NetC93_1 NetC93_2 RF_N RF_P
differential pair class 120E: NewDifferentialPair1 NewDifferentialPair2
differential pair class 100E: AR_LVDS_0 AR_LVDS_0_J AR_LVDS_0_R AR_LVDS_1 AR_LVDS_1_J AR_LVDS_1_R AR_LVDS_CLK AR_LVDS_CLK_J AR_LVDS_CLK_R AR_LVDS_FRCLK AR_LVDS_FRCLK_R X48M
differential pair class 90E: USB USB_R
component class PROC106B_RST_GPIOs_I2C: C6 C9 C10 C11 C12 C13 C38 C39 C72 C120 C125 J3 LD2 LD3 LD5 Q1 R13 R18 R38 R42 R51 R57 R67 R68 R69 R70 R71 R72 R73 R77 R78 R80 R81 R82 R93 R96 R97 R98 R107 R108 R111 R124 R125 R129 R177 R178 SW2 SW3 TP15 TP20 U5 U6 U7 U16 Y4
component class PROC106B_PMIC: C30 C31 C32 C33 C34 C44 C45 C46 C47 C48 C49 C50 C51 C52 C53 C54 C73 C75 C76 C77 C111 C112 C113 C121 C124 C131 L2 L3 L4 L5 L11 L12 L13 L14 LD1 R25 R26 R28 R31 R32 R33 R34 R35 R36 R37 R39 R50 R52 R53 R54 R55 R56 TP5 TP12 U1
component class PROC106B_HD_CONN_PWR_SW: C127 C128 C129 FL22 J2 J11 L16 R10 R11 R12 R14 R20 R24 R27 R29 R58 R88 R92 R130 R132 R133 R135 R137 R138 R140 R142 R143 R144 R145 R146 R147 R148 R149 R150 R151 R152 R153 R154 R155 R157 R186 R187 R188 R189 R190 RA1 RA2 RA3 RA4 RA5 RA6 RA7 RA8 RA9 TP10 TP13 U19
component class PROC106B_FLASH_USB_TO_UART: C1 C2 C3 C4 C100 C101 C126 D1 FL2 J1 LD4 R6 R15 R19 R40 R41 R43 R44 R45 R46 R47 R48 R49 R60 R61 R62 R63 R64 R65 TP18 TP19 TP26 U3 U9 U18
component class PROC106B_CAN_INTERFACE: C40 C43 C105 C106 C107 C108 C109 C110 FL3 FL12 J8 J10 R66 R74 R104 R105 R106 R114 R115 R116 R117 R118 R119 R120 R121 R122 R123 R126 R127 R128 R134 R136 R139 R141 U11 U12 U13 U17
component class PROC106B_BT_DISPLAY: A1 C5 C7 C8 C15 C16 C17 C18 C19 C20 C21 C22 C23 C24 C25 C26 C27 C28 C29 C35 C36 C37 C41 C86 C93 C99 C104 C114 C115 C116 C117 C118 C119 J4 J6 J7 L1 L6 L7 L8 L9 L10 LD6 R17 R30 R76 R79 R86 R87 R89 R90 R91 R94 R95 R99 R100 R101 R102 R110 R112 R113 R131 R160 R161 R166 R168 R180 R181 R182 R183 R184 R185 TP16 TP27 TP46 U4 U8 U10 U14 Y2 Y3
component class PROC106B_AOP_PWR: C55 C56 C57 C58 C59 C60 C61 C62 C63 C64 C65 C66 C67 C68 C69 C70 C74 C78 C79 C80 C81 C82 C83 C84 C85 C87 C88 C89 C90 C91 C92 C94 C95 C96 C97 C98 C102 C103 TP11
component class PROC106B_AOP_IO: C14 C71 C130 R2 R3 R4 R5 R7 R8 R9 R21 R22 R23 R59 R75 R83 R84 R85 R103 R158 R159 R170 R171 R172 R174 R176 S3 TP2 TP3 TP6 TP7 TP8 TP9 TP14 TP17 U2 Y1
component class PROC106B_ANALOG_MUX: C42 C122 C123 J5 L15 R1 R16 S1 S2 TP4 U15
component class PROC106B_Hardware: FID1 FID2 FID3 FID4 FID5 FID6 ZZ1 ZZ2 ZZ3 ZZ4 ZZ5.1 ZZ5.2
component class FiducialMark: Designator1_2 Designator7_1 Designator22_1 Designator23 FID1 FID2 FID3 FID4 FID5 FID6
component class AssemblyNote: ZZ1 ZZ2 ZZ3 ZZ4 ZZ5.1 ZZ5.2
differential pair NewDifferentialPair3: +X48M_P -X48M_N
differential pair AR_LVDS_CLK_J: +NetJ2_36 -NetJ2_34
differential pair AR_LVDS_1_J: +NetJ2_42 -NetJ2_40
differential pair AR_LVDS_0_J: +NetJ2_48 -NetJ2_46
differential pair USB_R: +NetR60_1 -NetR41_1
differential pair NewDifferentialPair1: +NetJ8_1 -NetJ8_3
differential pair USB: +USB_DP -USB_DM
differential pair NewDifferentialPair2: +NetJ10_1 -NetJ10_3
differential pair AR_LVDS_CLK: +AR_LVDS_CLK_P -AR_LVDS_CLK_N
differential pair AR_LVDS_FRCLK: +AR_LVDS_FRCLK_P -AR_LVDS_FRCLK_N
differential pair AR_LVDS_1: +AR_LVDS_1_P -AR_LVDS_1_N
differential pair AR_LVDS_0: +AR_LVDS_0_P -AR_LVDS_0_N
differential pair AR_LVDS_0_R: +NetJ11_56 -NetJ11_58
differential pair AR_LVDS_1_R: +NetJ11_50 -NetJ11_52
differential pair AR_LVDS_CLK_R: +NetJ11_44 -NetJ11_46
differential pair AR_LVDS_FRCLK_R: +NetJ11_26 -NetJ11_28

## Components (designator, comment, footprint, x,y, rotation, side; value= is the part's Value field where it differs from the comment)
A1 "ANT016008LCS2442MA2" FP-ANT016008LCS2442MA2_SMT_ANT-0 7284.33,4589.83 r180 top
C1 "GCM21BR71A106KE22L" 0805L 3004.01,3914.32 r270 top value=10uF
C2 "GCM155R71C104KA55D" 0402L 3005.89,4400.66 r180 bottom value=0.1uF
C3 "GCM155R71C104KA55D" 0402L 3005.89,4400.66 r180 top value=0.1uF
C4 "GCM21BR71A106KE22L" 0805L 3004.01,3914.26 r90 bottom value=10uF
C5 "CL03A105MO3NRNH" FP-CL03A105MO3NRNH_0201-IPC_C 6882.81,3977 r180 bottom
C6 "GRM033R6YA104KE14D" "FP-GRM033R6YA104KE14D_0201 (0603 Metric)-IPC_C" 5234.38,4538.7 r90 bottom
C7 "CL05A106MP5NUNC" 0402_070 6844.78,3720.79 r0 bottom value=10uF
C8 "CL03A103KA3NNNC" FP-CL03A103KA3NNNC_0201-IPC_C 6903.19,3719.01 r180 bottom
C9 "GRM033R6YA104KE14D" "FP-GRM033R6YA104KE14D_0201 (0603 Metric)-IPC_C" 5197.1,3791.56 r90 bottom locked
C10 "GRM033R6YA104KE14D" "FP-GRM033R6YA104KE14D_0201 (0603 Metric)-IPC_C" 5162.69,3875.17 r90 bottom
C11 "CL03A105MO3NRNH" FP-CL03A105MO3NRNH_0201-IPC_C 5172.1,3791.41 r270 bottom
C12 "GRM033R6YA104KE14D" "FP-GRM033R6YA104KE14D_0201 (0603 Metric)-IPC_C" 5580.92,3737.11 r0 bottom
C13 "GRM033R6YA104KE14D" "FP-GRM033R6YA104KE14D_0201 (0603 Metric)-IPC_C" 5242.93,4010.48 r0 bottom
C14 "CGA1A2C0G1H4R7C030BA" FP-CGA1A2C0G1H4R7C030BA_0201-IPC_C 4153.98,3817.27 r180 top value=4.7pF
C15 "CL03A105MO3NRNH" FP-CL03A105MO3NRNH_0201-IPC_C 4750.21,4143.82 r270 top
C16 "CL03A105MO3NRNH" FP-CL03A105MO3NRNH_0201-IPC_C 4713.47,4143.92 r270 top
C17 "GRM0335C1H8R0BA01D" "FP-GRM0335C1H8R0BA01D_0201 (0603 metric)-IPC_C" 6613.33,4250.88 r0 top
C18 "GRM0335C1H8R0BA01D" "FP-GRM0335C1H8R0BA01D_0201 (0603 metric)-IPC_C" 6634.87,4127.04 r180 top
C19 "250R05L120JV4T" FP-250R05L120JV4T_0201-IPC_C 6277.6,4370.87 r270 top
C20 "250R05L120JV4T" FP-250R05L120JV4T_0201-IPC_C 6277.6,4324.98 r90 top
C21 "CL05C120JB5NNNC" 0402L 6540.73,4344.09 r270 top value=12pF
C22 "GCM1555C1H1R0CA16D" 0402L 6468.51,4395.47 r270 top value=1pF
C23 "GCM1555C1H1R0CA16D" 0402L 6395.4,4324.42 r180 top value=1pF
C24 "CL03A105MO3NRNH" FP-CL03A105MO3NRNH_0201-IPC_C 6142.33,4003.46 r180 top
C25 "GRM033R6YA104KE14D" "FP-GRM033R6YA104KE14D_0201 (0603 Metric)-IPC_C" 6157.34,4271.39 r180 top
C26 "GRM033R6YA104KE14D" "FP-GRM033R6YA104KE14D_0201 (0603 Metric)-IPC_C" 6142.18,4042.21 r180 top
C27 "GRM033R6YA104KE14D" "FP-GRM033R6YA104KE14D_0201 (0603 Metric)-IPC_C" 6518.42,4103.16 r270 top
C28 "CL05A226MQ5N6J8" 0402S 6458.05,3903.24 r0 top
C29 "CL05A226MQ5N6J8" 0402S 6471.97,4137.37 r180 bottom
C30 "GCM155R71C224KE02D" 0402L 3295.87,4189 r90 top value=0.22uF
C31 "CGA2B2C0G1H391J050BA" 0402L 3667.5,4538.34 r180 top value=390pF
C32 "CGA2B2C0G1H391J050BA" 0402L 3200.34,4518.49 r0 top value=390pF
C33 "CGA2B2C0G1H391J050BA" 0402L 3615.39,4098.42 r270 top value=390pF
C34 "CGA2B2C0G1H391J050BA" 0402L 3231.35,3936.68 r270 top value=390pF
C35 "GRM033R6YA104KE14D" "FP-GRM033R6YA104KE14D_0201 (0603 Metric)-IPC_C" 6534.66,4138.22 r0 top
C36 "GRM033R6YA104KE14D" "FP-GRM033R6YA104KE14D_0201 (0603 Metric)-IPC_C" 6516.27,4239.23 r90 top
C37 "GRM033R6YA104KE14D" "FP-GRM033R6YA104KE14D_0201 (0603 Metric)-IPC_C" 6287.19,4411.08 r180 top
C38 "250R05L120JV4T" FP-250R05L120JV4T_0201-IPC_C 5245.41,3795.56 r180 bottom
C39 "250R05L120JV4T" FP-250R05L120JV4T_0201-IPC_C 5291.16,3795.56 r0 bottom
C40 "GRM033R6YA104KE14D" "FP-GRM033R6YA104KE14D_0201 (0603 Metric)-IPC_C" 6581.1,4040.29 r180 top
C41 "GCM1555C1H1R0CA16D" 0402L 6461.93,4540.91 r0 top value=1pF
C42 "CL05A106MP5NUNC" 0402_070 6821.81,4040 r90 top value=10uF
C43 "GRM033R6YA104KE14D" "FP-GRM033R6YA104KE14D_0201 (0603 Metric)-IPC_C" 5891.78,4292.07 r0 top
C44 "CGA4J1X7T0J226M125AC" FP-CGA4J1X7T0J226M125AC_0805-MFG 3516.1,4538.33 r0 top value=22µF
C45 "CGA4J1X7T0J226M125AC" FP-CGA4J1X7T0J226M125AC_0805-MFG 3336.18,4538.34 r180 top value=22µF
C46 "CGA4J1X7T0J226M125AC" FP-CGA4J1X7T0J226M125AC_0805-MFG 3514.81,3840.95 r0 top value=22µF
C47 "CGA4J1X7T0J226M125AC" FP-CGA4J1X7T0J226M125AC_0805-MFG 3335.76,3832.63 r180 top value=22µF
C48 "CGA4J1X7T0J226M125AC" FP-CGA4J1X7T0J226M125AC_0805-MFG 3335.76,3750.6 r180 top value=22µF
C49 "CGA4J1X7T0J226M125AC" FP-CGA4J1X7T0J226M125AC_0805-MFG 3514.81,3770.11 r0 top value=22µF
C50 "GCM21BR71A106KE22L" 0805_HV1 3355.89,4015.14 r0 top value=10uF
C51 "GCM21BR71A106KE22L" 0805_HV1 3495.89,4015.14 r180 top value=10uF
C52 "GCM21BR71A106KE22L" 0805_HV1 3357.86,4352.35 r0 top value=10uF
C53 "GCM21BR71A106KE22L" 0805_HV1 3495.89,4352.35 r180 top value=10uF
C54 "CGA4J1X7T0J226M125AC" FP-CGA4J1X7T0J226M125AC_0805-MFG 3514.81,3699.04 r0 top value=22µF
C55 "GCM21BR71A106KE22L" 0805L 3908.19,4239.7 r0 bottom value=10uF
C56 "GCM155R71C224KE02D" 0402L 4323.95,4419.07 r0 bottom value=0.22uF
C57 "GCM155R71C224KE02D" 0402L 3686.18,4257.19 r180 top value=0.22uF
C58 "GCM155R71C224KE02D" 0402L 3686.18,4218.19 r180 top value=0.22uF
C59 "GCM21BR71A106KE22L" 0805L 3700.56,4275.26 r90 bottom value=10uF
C60 "GCM155R71C224KE02D" 0402L 4309.75,4188.46 r90 bottom value=0.22uF
C61 "GCM155R71C224KE02D" 0402L 4018.33,4342.22 r270 bottom value=0.22uF
C62 "GCM21BR71A106KE22L" 0805L 4040,3970.52 r90 bottom value=10uF
C63 "GCM155R71C224KE02D" 0402L 3935.07,3856.83 r180 bottom value=0.22uF
C64 "GCM155R71C224KE02D" 0402L 3967.69,3945.83 r180 bottom value=0.22uF
C65 "GCM21BR71A106KE22L" 0805L 3674.97,3943.67 r180 bottom value=10uF
C66 "GCM155R71C224KE02D" 0402L 3865.49,3945.78 r90 bottom value=0.22uF
C67 "GCM155R71C224KE02D" 0402L 3790.94,3955.68 r0 bottom value=0.22uF
C68 "GCM155R71C224KE02D" 0402L 3713.57,3943.79 r90 top value=0.22uF
C69 "CGA2B3X7R1H473K050BB" 0402L 3822.75,3862.61 r180 bottom value=0.047uF
C70 "GCM21BR71A106KE22L" 0805L 3908.19,4023.7 r0 bottom value=10uF
C71 "CGA1A2C0G1H4R7C030BA" FP-CGA1A2C0G1H4R7C030BA_0201-IPC_C 4106.98,3817.45 r180 top value=4.7pF
C72 "GRM033R6YA104KE14D" "FP-GRM033R6YA104KE14D_0201 (0603 Metric)-IPC_C" 4845,4415.28 r0 top
C73 "CGA4J1X7T0J226M125AC" FP-CGA4J1X7T0J226M125AC_0805-MFG 3299.16,3669 r180 top value=22µF
C74 "GCM188R70J225KE22D" 0603L 3687.18,4009.15 r180 top value=2.2uF
C75 "CGA4J1X7T0J226M125AC" FP-CGA4J1X7T0J226M125AC_0805-MFG 3702.01,3803.74 r0 bottom value=22µF
C76 "GCM21BR71A106KE22L" 0805L 3427.48,4623.45 r0 bottom value=10uF
C77 "CGA4J1X7T0J226M125AC" FP-CGA4J1X7T0J226M125AC_0805-MFG 3136,4614 r0 top value=22µF
C78 "GCM21BR71A106KE22L" 0805L 3908.19,4167.7 r0 bottom value=10uF
C79 "GCM188R70J225KE22D" 0603L 3710.6,4167.45 r90 bottom value=2.2uF
C80 "GCM155R71C224KE02D" 0402L 3686.2,4141.13 r180 top value=0.22uF
C81 "GCM155R71C224KE02D" 0402L 3686.2,4177.66 r180 top value=0.22uF
C82 "GCM21BR71A106KE22L" 0805L 3908.19,4095.7 r0 bottom value=10uF
C83 "GCM188R70J225KE22D" 0603L 3655.22,4120.08 r90 bottom value=2.2uF
C84 "GCM155R71C224KE02D" 0402L 3687.73,4060.46 r180 top value=0.22uF
C85 "GCM155R71C224KE02D" 0402L 3687.73,4097.51 r180 top value=0.22uF
C86 "GRM033R6YA104KE14D" "FP-GRM033R6YA104KE14D_0201 (0603 Metric)-IPC_C" 6410.84,3907.91 r270 top
C87 "GCM155R71C224KE02D" 0402L 4314.32,4094.43 r270 bottom value=0.22uF
C88 "GCM155R71C224KE02D" 0402L 4085.98,4438.9 r90 bottom value=0.22uF
C89 "GCM188R71C105KA64D" 0603L 4132.97,3811.96 r0 bottom value=1uF
C90 "GCM188R71C105KA64D" 0603L 4028.67,3857.43 r180 bottom value=1uF
C91 "GCM155R71C104KA55D" 0402L 4218.02,4377.65 r90 bottom value=0.1uF
C92 "GCM155R71C104KA55D" 0402L 4352.69,4188.46 r270 bottom value=0.1uF
C93 "CL05C120JB5NNNC" 0402L 6586.38,4589.83 r180 top value=12pF
C94 "GCM155R71C224KE02D" 0402L 4364,3874.31 r270 bottom value=0.22uF
C95 "GCM155R71C224KE02D" 0402L 4376.53,3958.4 r270 bottom value=0.22uF
C96 "GCM155R71C224KE02D" 0402L 4094.31,4356.14 r270 bottom value=0.22uF
C97 "GCM155R71C224KE02D" 0402L 4188.97,3908.47 r90 bottom value=0.22uF
C98 "GCM155R71C224KE02D" 0402L 3918.65,4396.76 r0 bottom value=0.22uF
C99 "GJM1555C1H1R8BB01D" 0402L 7156.66,4589.69 r180 top value=1.8pF
C100 "GCM188R71C105KA64D" 0603L 3220.18,4028.4 r90 top value=1uF
C101 "GCM155R71C104KA55D" 0402L 3257.08,4075.84 r270 bottom value=0.1uF
C102 "GCM188R70J225KE22D" 0603L 4367.44,4062.4 r270 bottom value=2.2uF
C103 "GCM188R70J225KE22D" 0603L 4150.97,4365.07 r270 bottom value=2.2uF
C104 "GJM1555C1H1R8BB01D" 0402L 7217.64,4570.15 r270 top value=1.8pF
C105 "GRM033R6YA104KE14D" "FP-GRM033R6YA104KE14D_0201 (0603 Metric)-IPC_C" 6003.64,4429.32 r90 top
C106 "GRM155R71H472KA01D" 0402L 6042.33,4472.32 r90 top value=4700pF
C107 "GRM033R6YA104KE14D" "FP-GRM033R6YA104KE14D_0201 (0603 Metric)-IPC_C" 6735.03,4433.22 r90 top
C108 "GRM033R6YA104KE14D" "FP-GRM033R6YA104KE14D_0201 (0603 Metric)-IPC_C" 6709.78,3866.01 r270 top
C109 "GRM033R6YA104KE14D" "FP-GRM033R6YA104KE14D_0201 (0603 Metric)-IPC_C" 6877.41,3768.9 r0 top
C110 "GRM155R71H472KA01D" 0402L 6951.81,3773.61 r90 top value=4700pF
C111 "CGA4J1X7T0J226M125AC" FP-CGA4J1X7T0J226M125AC_0805-MFG 3639.35,3729.75 r180 bottom value=22µF
C112 "GCM21BR71A106KE22L" 0805L 3109.68,3663.43 r180 top value=10uF
C113 "GCM21BR71A106KE22L" 0805L 3638.2,3839.06 r90 top value=10uF
C114 "GRM033R6YA104KE14D" "FP-GRM033R6YA104KE14D_0201 (0603 Metric)-IPC_C" 6174.57,3747.34 r180 bottom
C115 "CL03A105MO3NRNH" FP-CL03A105MO3NRNH_0201-IPC_C 5764.72,3872.2 r0 top
C116 "CL03A105MO3NRNH" FP-CL03A105MO3NRNH_0201-IPC_C 5764.72,3843.74 r0 top
C117 "GRM033R6YA104KE14D" "FP-GRM033R6YA104KE14D_0201 (0603 Metric)-IPC_C" 6050.15,3984.72 r90 top
C118 "GRM033R6YA104KE14D" "FP-GRM033R6YA104KE14D_0201 (0603 Metric)-IPC_C" 6272.5,3733.87 r270 bottom
C119 "GRM033R6YA104KE14D" "FP-GRM033R6YA104KE14D_0201 (0603 Metric)-IPC_C" 6304.91,3909.21 r90 bottom
C120 "GRM033R6YA104KE14D" "FP-GRM033R6YA104KE14D_0201 (0603 Metric)-IPC_C" 4905.18,4369.7 r0 top
C121 "GCM21BR71A106KE22L" 0805L 3541.25,3686.2 r270 bottom value=10uF
C122 "CL05A106MP5NUNC" 0402_070 6771.81,4040 r270 top value=10uF
C123 "GRM033R6YA104KE14D" "FP-GRM033R6YA104KE14D_0201 (0603 Metric)-IPC_C" 5580.17,4531.94 r270 top
C124 "CGA4J1X7T0J226M125AC" FP-CGA4J1X7T0J226M125AC_0805-MFG 3702.01,3871.27 r0 bottom value=22µF
C125 "CL03A103KA3NNNC" FP-CL03A103KA3NNNC_0201-IPC_C 5252.95,4538.7 r270 bottom
C126 "GCM155R71C104KA55D" 0402L 3691.38,4365.53 r180 top value=0.1uF
C127 "GRM033R6YA104KE14D" "FP-GRM033R6YA104KE14D_0201 (0603 Metric)-IPC_C" 6653.18,3936.75 r180 bottom
C128 "GRM033R6YA104KE14D" "FP-GRM033R6YA104KE14D_0201 (0603 Metric)-IPC_C" 6643.28,3766.12 r180 bottom
C129 "CL03A105MO3NRNH" FP-CL03A105MO3NRNH_0201-IPC_C 6719.58,3813.74 r270 bottom
C130 "GCM155R71C104KA55D" 0402L 3967.83,4318.05 r90 bottom value=0.1uF
C131 "CGA4J1X7T0J226M125AC" FP-CGA4J1X7T0J226M125AC_0805-MFG 3469.55,3689.64 r90 bottom value=22µF
D1 "NRVB230LSFT1G" FP-NRVB230LSFT1G_SOD-123F-MFG 3134.01,3940.99 r90 top
Designator1 "Comment" MHNP_M2_PANHEAD_PHILLIPS 2983.52,4883.72 r0 top
Designator1_1 "BRAKE_WAY_HOLES1X2" BRAKE_WAY_HOLES1X2 3205.41,3572.64 r180 bottom
Designator1_2 "Comment" MHNP_M2_PANHEAD_PHILLIPS 2969.58,4541.42 r0 top
Designator2 "BRAKE_WAY_HOLES1X2" BRAKE_WAY_HOLES1X2 4188.97,4725.69 r180 top
Designator2_1 "BRAKE_WAY_HOLES1X2" BRAKE_WAY_HOLES1X2 6010.52,3609.79 r180 bottom
Designator3 "BRAKE_WAY_HOLES1X2" BRAKE_WAY_HOLES1X2 3697.19,4725.69 r180 top
Designator3_2 "BRAKE_WAY_HOLES1X2" BRAKE_WAY_HOLES1X2 5469.11,4687.74 r0 bottom
Designator4 "BRAKE_WAY_HOLES1X2" BRAKE_WAY_HOLES1X2 4706.5,3609.79 r0 top
Designator4_1 "BRAKE_WAY_HOLES1X2" BRAKE_WAY_HOLES1X2 3697.19,3572.64 r180 bottom
Designator5 "BRAKE_WAY_HOLES1X2" BRAKE_WAY_HOLES1X2 7157.87,4687.69 r180 top
Designator5_1 "BRAKE_WAY_HOLES1X2" BRAKE_WAY_HOLES1X2 7157.6,3609.79 r180 bottom
Designator5_2 "BRAKE_WAY_HOLES1X2" BRAKE_WAY_HOLES1X2 4188.97,3572.64 r180 bottom
Designator6 "Comment" MHNP_M2_PANHEAD_PHILLIPS 7259.4,4883.72 r0 top
Designator7 "Comment" MHNP_M2_PANHEAD_PHILLIPS 2983.52,3406.7 r0 top
Designator7_1 "Comment" MHNP_M2_PANHEAD_PHILLIPS 2969.58,3756.91 r0 top
Designator8 "Comment" MHNP_M2_PANHEAD_PHILLIPS 7259.4,3406.7 r0 top
Designator10 "BRAKE_WAY_HOLES1X2" BRAKE_WAY_HOLES1X2 3205.41,4725.69 r180 top
Designator22_1 "Comment" MHNP_2-5 6425,3754.06 r0 bottom
Designator23 "Comment" MHNP_2-5 5014.62,3754.06 r0 bottom
FID1 "Fiducial" FIDUCIAL6.4-20 3133.52,3406.7 r0 top
FID2 "Fiducial" FIDUCIAL6.4-20 3133.52,4883.72 r0 top
FID3 "Fiducial" FIDUCIAL6.4-20 7109.4,3406.7 r0 top
FID4 "Fiducial" FIDUCIAL6.4-20 7109.4,3406.7 r180 bottom
FID5 "Fiducial" FIDUCIAL6.4-20 3133.52,4883.72 r180 bottom
FID6 "Fiducial" FIDUCIAL6.4-20 3133.52,3406.7 r180 bottom
FL2 "BLM15PD300SZ1D" 0402L 3134.06,4077.41 r270 top
FL3 "BLM15PD300SZ1D" 0402L 6670.79,3868.56 r90 top
FL12 "BLM15PD300SZ1D" 0402L 5955.92,4292.41 r0 top
FL22 "BLM15PD300SZ1D" 0402L 4827.36,4588.36 r0 top
J1 "105017-0001" CONN_105017-0001 2979.51,4149.15 r90 bottom
J2 "QSH-030-01-L-D-A" Samtec_QSH-030-01-X-D-A 4733.36,4144.5 r0 bottom locked
J3 "M50-3930442" FP-M50-3930442_HDR4-RECOMMENDED_LAND_PATTERN 5065.29,4621.12 r0 bottom
J4 "51441-1093" FP-51441-1093_CONN_SMD_FFC-0 4585.45,4173.34 r270 top locked
J5 "PJ-051AH" CUI_PJ-051AH 7229.96,4179.69 r0 top
J6 "51441-1093" FP-51441-1093_CONN_SMD_FFC-0 5711.91,3740.17 r0 top
J7 "GRPB052MWCN-RC" FP-GRPB052MWCN-RC_HDR10-MFG 6233.84,4610.83 r180 top
J8 "M50-3930342" FP-M50-3930342_HDR3-MFG 5923.44,4618.25 r180 top
J10 "M50-3930342" FP-M50-3930342_HDR3-MFG 7329.6,3800 r90 top
J11 "QSH-030-01-L-D-A" Samtec_QSH-030-01-X-D-A 5895.12,4104.5 r180 bottom locked
L1 "LQG15HS2N4S02D" IND_LQG15H 6487.22,4324.41 r0 top value=2.4nH
L2 "DFE252012PD-R47M" DFE252012P 3535.79,4447.85 r180 top value=470nH
L3 "DFE252012PD-R47M" DFE252012P 3319.27,4447.85 r0 top value=470nH
L4 "DFE252012PD-R47M" DFE252012P 3530.36,3924.63 r180 top value=470nH
L5 "DFE252012PD-R47M" DFE252012P 3323.75,3924.63 r0 top value=470nH
L6 "LQG15HS2N4S02D" IND_LQG15H 6415.18,4396.46 r90 top value=2.4nH
L7 "MLZ2012N6R8LT000" 0805_HV 6491.96,4040.83 r90 bottom value=6.8uH
L8 "BLM18HE152SN1D" 0603L 6552.57,3919.1 r90 top value="1500 ohm"
L9 "LQG15HS2N0S02D" IND_LQG15H 6441.85,4484.72 r90 top value=2nH
L10 "LQG15HS2N0S02D" IND_LQG15H 6506.46,4589.83 r0 top value=2nH
L11 "MPZ2012S101ATD25" FP-MPZ2012S101ATD25_0805-MFG 3191.81,3746.61 r180 top
L12 "BLM18KG121TH1D" 0603_HV 3641.39,3714.72 r90 top value="120 ohm"
L13 "MPZ2012S101ATD25" FP-MPZ2012S101ATD25_0805-MFG 3287.13,4612.77 r0 top
L14 "BLM18KG121TH1D" 0603_HV 3647.19,3662.86 r180 bottom value="120 ohm"
L15 "MPZ2012S101ATD25" FP-MPZ2012S101ATD25_0805-MFG 6850.96,4138.99 r270 top
L16 "MPZ2012S101ATD25" FP-MPZ2012S101ATD25_0805-MFG 4763.29,3786.02 r270 top
LD1 "APHHS1005CGCK" APHHS1005_Green 2926.36,3943.79 r0 top value=Green
LD2 "APHHS1005CGCK" APHHS1005_Green 5272.84,4522.72 r270 top value=Green
LD3 "APHHS1005CGCK" APHHS1005_Green 4997.02,4522.72 r0 top value=Green
LD4 "APHHS1005CGCK" APHHS1005_Green 3246.44,4191.13 r270 bottom value=Green
LD5 "APHHS1005CGCK" APHHS1005_Green 4660.11,4457.37 r90 top value=Green
LD6 "APHHS1005CGCK" APHHS1005_Green 6227.85,4392.84 r90 top value=Green
Q1 "BSS123-7-F" FP-BSS123-7-F_SOT23-IPC_C 4750.81,4475.09 r180 top
R1 "RR0306P-103-D" FP-RR0306P-103-D_0201-IPC_C#1 5643.17,4618.56 r180 top
R2 "ERJ-1GN0R00C" 0201L 4106.92,4300.76 r180 bottom value=0
R3 "ERA-1AEB103C" FP-ERA-1AEB103C_0201-IPC_C 4274.79,3889.16 r180 bottom value=10k
R4 "ERJ-1GNF1003C" FP-ERJ-1GNF1003C_0201-IPC_C 3752.34,4408.84 r270 bottom value=100k
R5 "ERJ-1GNF1003C" FP-ERJ-1GNF1003C_0201-IPC_C 3752.34,4455.46 r90 bottom value=100k
R6 "ERJ-1GNF33R2C" FP-ERJ-1GNF33R2C_0201-IPC_C 3095.35,4050.45 r270 bottom value=33.2
R7 "ERA-1AEB103C" FP-ERA-1AEB103C_0201-IPC_C 4329.25,4017.43 r270 bottom value=10k
R8 "ERA-1AEB103C" FP-ERA-1AEB103C_0201-IPC_C 4221.23,4034.41 r270 bottom value=10k
R9 "ERJ-1GNF1003C" FP-ERJ-1GNF1003C_0201-IPC_C 4250.53,3921.56 r270 bottom value=100k
R10 "AC0201FR-0720RL" FP-AC0201FR-0720RL_0201-IPC_C 4917.01,3921 r180 bottom
R11 "AC0201FR-0720RL" FP-AC0201FR-0720RL_0201-IPC_C 4950.01,3937.94 r180 bottom
R12 "RC0201JR-070RL" "FP-RC0201JR-070RL_0201 (0603 Metric)-MFG" 4546.15,4434.59 r180 bottom
R13 "RC0201JR-07220RL" 0201L 5261.81,4570.64 r0 top value=220
R14 "RC0201JR-070RL" "FP-RC0201JR-070RL_0201 (0603 Metric)-MFG" 4547.12,4410.25 r180 bottom
R15 "ERJ-1GNJ221C" FP-ERJ-1GNJ221C_0201-IPC_C 3206.52,4166.71 r90 bottom value=220
R16 "RC0201FR-077K87L" 0201L 5566.39,4484.46 r180 top value=7.87k
R17 "RC0201JR-07220RL" 0201L 6227.85,4327.64 r90 top value=220
R18 "RR0306P-103-D" FP-RR0306P-103-D_0201-IPC_C#1 5362.78,4021.8 r270 bottom
R19 "ERA-1AEB103C" FP-ERA-1AEB103C_0201-IPC_C 3610.73,4577.6 r180 bottom value=10k
R20 "RR0306P-103-D" FP-RR0306P-103-D_0201-IPC_C#1 6584.18,3988.94 r180 bottom
R21 "ERA-1AEB103C" FP-ERA-1AEB103C_0201-IPC_C 3859.46,4298.05 r270 bottom value=10k
R22 "ERA-1AEB103C" FP-ERA-1AEB103C_0201-IPC_C 3886.73,4298.05 r270 bottom value=10k
R23 "ERA-1AEB103C" FP-ERA-1AEB103C_0201-IPC_C 3913.05,4298.05 r270 bottom value=10k
R24 "CRCW0402200RFKEDHP" FP-CRCW0402200RFKEDHP_0402-IPC_C 6583.18,3937.46 r180 bottom
R25 "ERJ-1GNF4991C" FP-ERJ-1GNF4991C_0201-IPC_C 3301.93,4243.48 r180 top value=4.99k
R26 "ERJ-1GNF4991C" FP-ERJ-1GNF4991C_0201-IPC_C 3295.24,4131.09 r180 top value=4.99k
R27 "RC0201JR-07510RL" 0201L 6606.39,3752.54 r90 bottom value=510
R28 "ERJ-1GN0R00C" 0201L 3555.87,4218.48 r180 top value=0
R29 "CRCW0201100KFKED" 0201L 6584.18,3965.94 r180 bottom value=100k
R30 "RC0201JR-070RL" "FP-RC0201JR-070RL_0201 (0603 Metric)-MFG" 5946.67,3893.52 r90 top
R31 "ERJ-1GN0R00C" 0201L 5008.05,3971.4 r180 bottom value=0
R32 "ERJ-1GN0R00C" 0201L 3558.22,4185.79 r180 top value=0
R33 "ERJ-1GNF4991C" FP-ERJ-1GNF4991C_0201-IPC_C 3295.5,4095.96 r180 top value=4.99k
R34 "ERJ-1GNF4991C" FP-ERJ-1GNF4991C_0201-IPC_C 3546.86,4253.13 r0 top value=4.99k
R35 "ERA-1AEB103C" FP-ERA-1AEB103C_0201-IPC_C 3301.93,4284.61 r180 top value=10k
R36 "ERA-1AEB103C" FP-ERA-1AEB103C_0201-IPC_C 3546.86,4139.79 r0 top value=10k
R37 "ERJ-1GNF1003C" FP-ERJ-1GNF1003C_0201-IPC_C 5007.04,4011.07 r180 bottom value=100k
R38 "RC0201FR-074K99L" 0201L 5330.47,4478.82 r180 bottom value=4.99k
R39 "ERJ-1GNJ511C" FP-ERJ-1GNJ511C_0201-IPC_C 2919.28,3885.59 r180 top value=510
R40 "ERJ-1GNF4991C" FP-ERJ-1GNF4991C_0201-IPC_C 3175.78,4488.13 r270 bottom value=4.99k
R41 "ERJ-1GN0R00C" 0201L 3013.92,4326.25 r180 bottom value=0
R42 "RC0201JR-07220RL" 0201L 5090.29,4522.72 r0 top value=220
R43 "ERA-1AEB103C" FP-ERA-1AEB103C_0201-IPC_C 3245.35,3734.95 r270 bottom value=10k
R44 "ERA-1AEB103C" FP-ERA-1AEB103C_0201-IPC_C 3095.98,3724.94 r180 bottom value=10k
R45 "ERA-1AEB103C" FP-ERA-1AEB103C_0201-IPC_C 3195.34,4097.11 r90 bottom value=10k
R46 "ERJ-1GNF33R2C" FP-ERJ-1GNF33R2C_0201-IPC_C 3195.35,3734.95 r90 bottom value=33.2
R47 "ERJ-1GNF33R2C" FP-ERJ-1GNF33R2C_0201-IPC_C 3145.35,4050.45 r270 bottom value=33.2
R48 "ERJ-1GNF33R2C" FP-ERJ-1GNF33R2C_0201-IPC_C 3145.35,3734.95 r90 bottom value=33.2
R49 "ERJ-1GNF33R2C" FP-ERJ-1GNF33R2C_0201-IPC_C 3195.35,4050.45 r270 bottom value=33.2
R50 "ERJ-1GNJ102C" FP-ERJ-1GNJ102C_0201-IPC_C 3241.63,4329.43 r90 top value=1k
R51 "RC0201JR-070RL" "FP-RC0201JR-070RL_0201 (0603 Metric)-MFG" 5327.6,4601.84 r0 bottom
R52 "ERJ-1GNF1961C" FP-ERJ-1GNF1961C_0201-IPC_C 3231.08,4281.06 r0 top value=1.96k
R53 "CRCW04023R83FKED" 0402L 3667.5,4501.24 r180 top value=3.83
R54 "CRCW04023R83FKED" 0402L 3200.34,4485.56 r0 top value=3.83
R55 "CRCW04023R83FKED" 0402L 3615.39,4020.22 r270 top value=3.83
R56 "CRCW04023R83FKED" 0402L 3231.35,3858.36 r270 top value=3.83
R57 "RC0201JR-070RL" "FP-RC0201JR-070RL_0201 (0603 Metric)-MFG" 5270.8,4602.69 r0 bottom
R58 "RC0201JR-070RL" "FP-RC0201JR-070RL_0201 (0603 Metric)-MFG" 5008.99,4046.94 r180 bottom
R59 "ERA-1AEB103C" FP-ERA-1AEB103C_0201-IPC_C 3936.98,4298.05 r270 bottom value=10k
R60 "ERJ-1GN0R00C" 0201L 3014.55,4356.6 r180 bottom value=0
R61 "ERJ-1GN0R00C" 0201L 3163.55,4206.75 r90 bottom value=0
R62 "ERJ-1GN0R00C" 0201L 3206.51,4580.21 r270 bottom value=0
R63 "ERJ-1GN0R00C" 0201L 3255.87,4579.81 r270 bottom value=0
R64 "ERJ-1GNF4991C" FP-ERJ-1GNF4991C_0201-IPC_C 3086.14,4475.15 r0 bottom value=4.99k
R65 "ERA-1AEB103C" FP-ERA-1AEB103C_0201-IPC_C 3137.8,4475.15 r180 bottom value=10k
R66 "RC0201JR-070RL" "FP-RC0201JR-070RL_0201 (0603 Metric)-IPC_C" 4991.42,4377.56 r0 bottom
R67 "RC0201JR-070RL" "FP-RC0201JR-070RL_0201 (0603 Metric)-MFG" 5513.34,3938.91 r0 bottom
R68 "RC0201JR-070RL" "FP-RC0201JR-070RL_0201 (0603 Metric)-MFG" 5601.88,3937.06 r180 bottom
R69 "RC0201FR-074K99L" 0201L 5505.11,3737.11 r180 bottom value=4.99k
R70 "RC0201JR-070RL" "FP-RC0201JR-070RL_0201 (0603 Metric)-MFG" 5434,3877.69 r0 bottom
R71 "RC0201JR-070RL" "FP-RC0201JR-070RL_0201 (0603 Metric)-MFG" 5396.26,3801.26 r0 bottom
R72 "RC0201JR-070RL" "FP-RC0201JR-070RL_0201 (0603 METRIC)-IPC_C" 5422.76,3927.24 r270 bottom
R73 "RC0201JR-070RL" "FP-RC0201JR-070RL_0201 (0603 METRIC)-IPC_C" 5458.86,3908 r180 bottom
R74 "RC0201JR-070RL" "FP-RC0201JR-070RL_0201 (0603 METRIC)-IPC_C" 6581.1,4063.92 r0 top
R75 "ERJ-1GNJ102C" FP-ERJ-1GNJ102C_0201-IPC_C 4300.76,3981.67 r270 bottom value=1k
R76 "RC0201JR-070RL" "FP-RC0201JR-070RL_0201 (0603 METRIC)-IPC_C" 6210.78,3903.45 r90 bottom
R77 "RR0306P-103-D" FP-RR0306P-103-D_0201-IPC_C#1 5185.3,4021 r270 bottom
R78 "RR0306P-103-D" FP-RR0306P-103-D_0201-IPC_C#1 5155,3984 r0 bottom
R79 "ERJ-1GNF4701C" FP-ERJ-1GNF4701C_0201-IPC_C 6304.11,3815.65 r270 bottom
R80 "RR0306P-103-D" FP-RR0306P-103-D_0201-IPC_C#1 5155.48,3915 r0 bottom
R81 "RR0306P-103-D" FP-RR0306P-103-D_0201-IPC_C#1 5324.41,4050.42 r270 bottom
R82 "RR0306P-103-D" FP-RR0306P-103-D_0201-IPC_C#2 5279.72,4021 r270 bottom
R83 "ERA-1AEB103C" FP-ERA-1AEB103C_0201-IPC_C 4055.26,4296.88 r270 bottom value=10k
R84 "ERA-1AEB103C" FP-ERA-1AEB103C_0201-IPC_C 4216.3,4208.84 r90 bottom value=10k
R85 "ERA-1AEB103C" FP-ERA-1AEB103C_0201-IPC_C 3645.85,4457.99 r270 top value=10k
R86 "RC0201JR-070RL" "FP-RC0201JR-070RL_0201 (0603 METRIC)-IPC_C" 6141.03,4180.57 r0 top
R87 "RC0201JR-070RL" "FP-RC0201JR-070RL_0201 (0603 METRIC)-IPC_C" 6141.18,4202.46 r0 top
R88 "AC0201FR-0720RL" FP-AC0201FR-0720RL_0201-IPC_C 4547.27,4114.97 r0 bottom
R89 "CRCW0201100KFKED" 0201L 6338.19,4411.08 r0 top value=100k
R90 "RC0201JR-070RL" "FP-RC0201JR-070RL_0201 (0603 METRIC)-IPC_C" 6278.99,4249 r0 bottom
R91 "RC0201JR-070RL" "FP-RC0201JR-070RL_0201 (0603 METRIC)-IPC_C" 6422.16,3920.53 r180 bottom
R92 "CRCW0201100KFKED" 0201L 6583.22,3689.74 r0 bottom value=100k
R93 "RR0306P-103-D" FP-RR0306P-103-D_0201-IPC_C#1 5206.3,4021 r90 bottom
R94 "RR0306P-103-D" FP-RR0306P-103-D_0201-IPC_C#1 5995.7,4043.69 r0 top
R95 "RR0306P-103-D" FP-RR0306P-103-D_0201-IPC_C#1 5979.95,3836.09 r0 top
R96 "RR0306P-103-D" FP-RR0306P-103-D_0201-IPC_C#1 5155.48,3938 r180 bottom
R97 "RC0201JR-070RL" "FP-RC0201JR-070RL_0201 (0603 METRIC)-IPC_C" 5314.73,4010.48 r0 bottom
R98 "RR0306P-103-D" FP-RR0306P-103-D_0201-IPC_C#1 5155,3961 r180 bottom
R99 "RC0201JR-070RL" "FP-RC0201JR-070RL_0201 (0603 METRIC)-IPC_C" 5996.83,3891.7 r270 top
R100 "RC0201JR-070RL" "FP-RC0201JR-070RL_0201 (0603 METRIC)-IPC_C" 5872.42,3998.82 r0 top
R101 "RC0201JR-070RL" "FP-RC0201JR-070RL_0201 (0603 METRIC)-IPC_C" 6046.19,3941.56 r270 top
R102 "RC0201JR-070RL" "FP-RC0201JR-070RL_0201 (0603 METRIC)-IPC_C" 6278.99,4272.45 r0 bottom
R103 "ERJ-1GN0R00C" 0201L 3679.35,4459.54 r270 top value=0
R104 "RR0306P-103-D" FP-RR0306P-103-D_0201-IPC_C#1 6581.47,4005 r180 top
R105 "RC0201JR-070RL" "FP-RC0201JR-070RL_0201 (0603 METRIC)-IPC_C" 6685.03,3997.34 r180 top
R106 "RC0201JR-070RL" "FP-RC0201JR-070RL_0201 (0603 METRIC)-IPC_C" 6695.04,4036.52 r90 top
R107 "RC0201JR-07510RL" 0201L 4620.57,4450.68 r270 top value=510
R108 "RC0201JR-07510RL" 0201L 4843.99,4439.06 r180 top value=510
R110 "RR0306P-103-D" FP-RR0306P-103-D_0201-IPC_C#1 6168.27,4114.75 r270 bottom
R111 "RC0201JR-07220RL" 0201L 5100.51,4345.88 r180 top value=220
R112 "RC0201JR-070RL" "FP-RC0201JR-070RL_0201 (0603 METRIC)-IPC_C" 5872.42,3951.7 r0 top
R113 "RC0201JR-070RL" "FP-RC0201JR-070RL_0201 (0603 METRIC)-IPC_C" 5914.31,3891.7 r90 top
R114 "CRCW040261R9FKED" 0402L 6930.63,3895.33 r180 top value=61.9
R115 "RC0201JR-070RL" "FP-RC0201JR-070RL_0201 (0603 Metric)-IPC_C" 6854.79,3961 r0 top
R116 "RC0201JR-070RL" "FP-RC0201JR-070RL_0201 (0603 Metric)-IPC_C" 6754.79,3956 r0 top
R117 "CRCW040261R9FKED" 0402L 6909.66,3823.52 r270 top value=61.9
R118 "RR0306P-103-D" FP-RR0306P-103-D_0201-IPC_C#1 6696.81,4422 r90 top
R119 "CRCW040261R9FKED" 0402L 5885.96,4492.77 r0 top value=61.9
R120 "RC0201JR-070RL" "FP-RC0201JR-070RL_0201 (0603 Metric)-IPC_C" 6802.81,4252.99 r90 top
R121 "RC0201JR-070RL" "FP-RC0201JR-070RL_0201 (0603 METRIC)-IPC_C" 6649.04,4333.23 r180 top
